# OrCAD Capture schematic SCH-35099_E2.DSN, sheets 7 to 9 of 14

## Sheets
7 03 System Power: size C
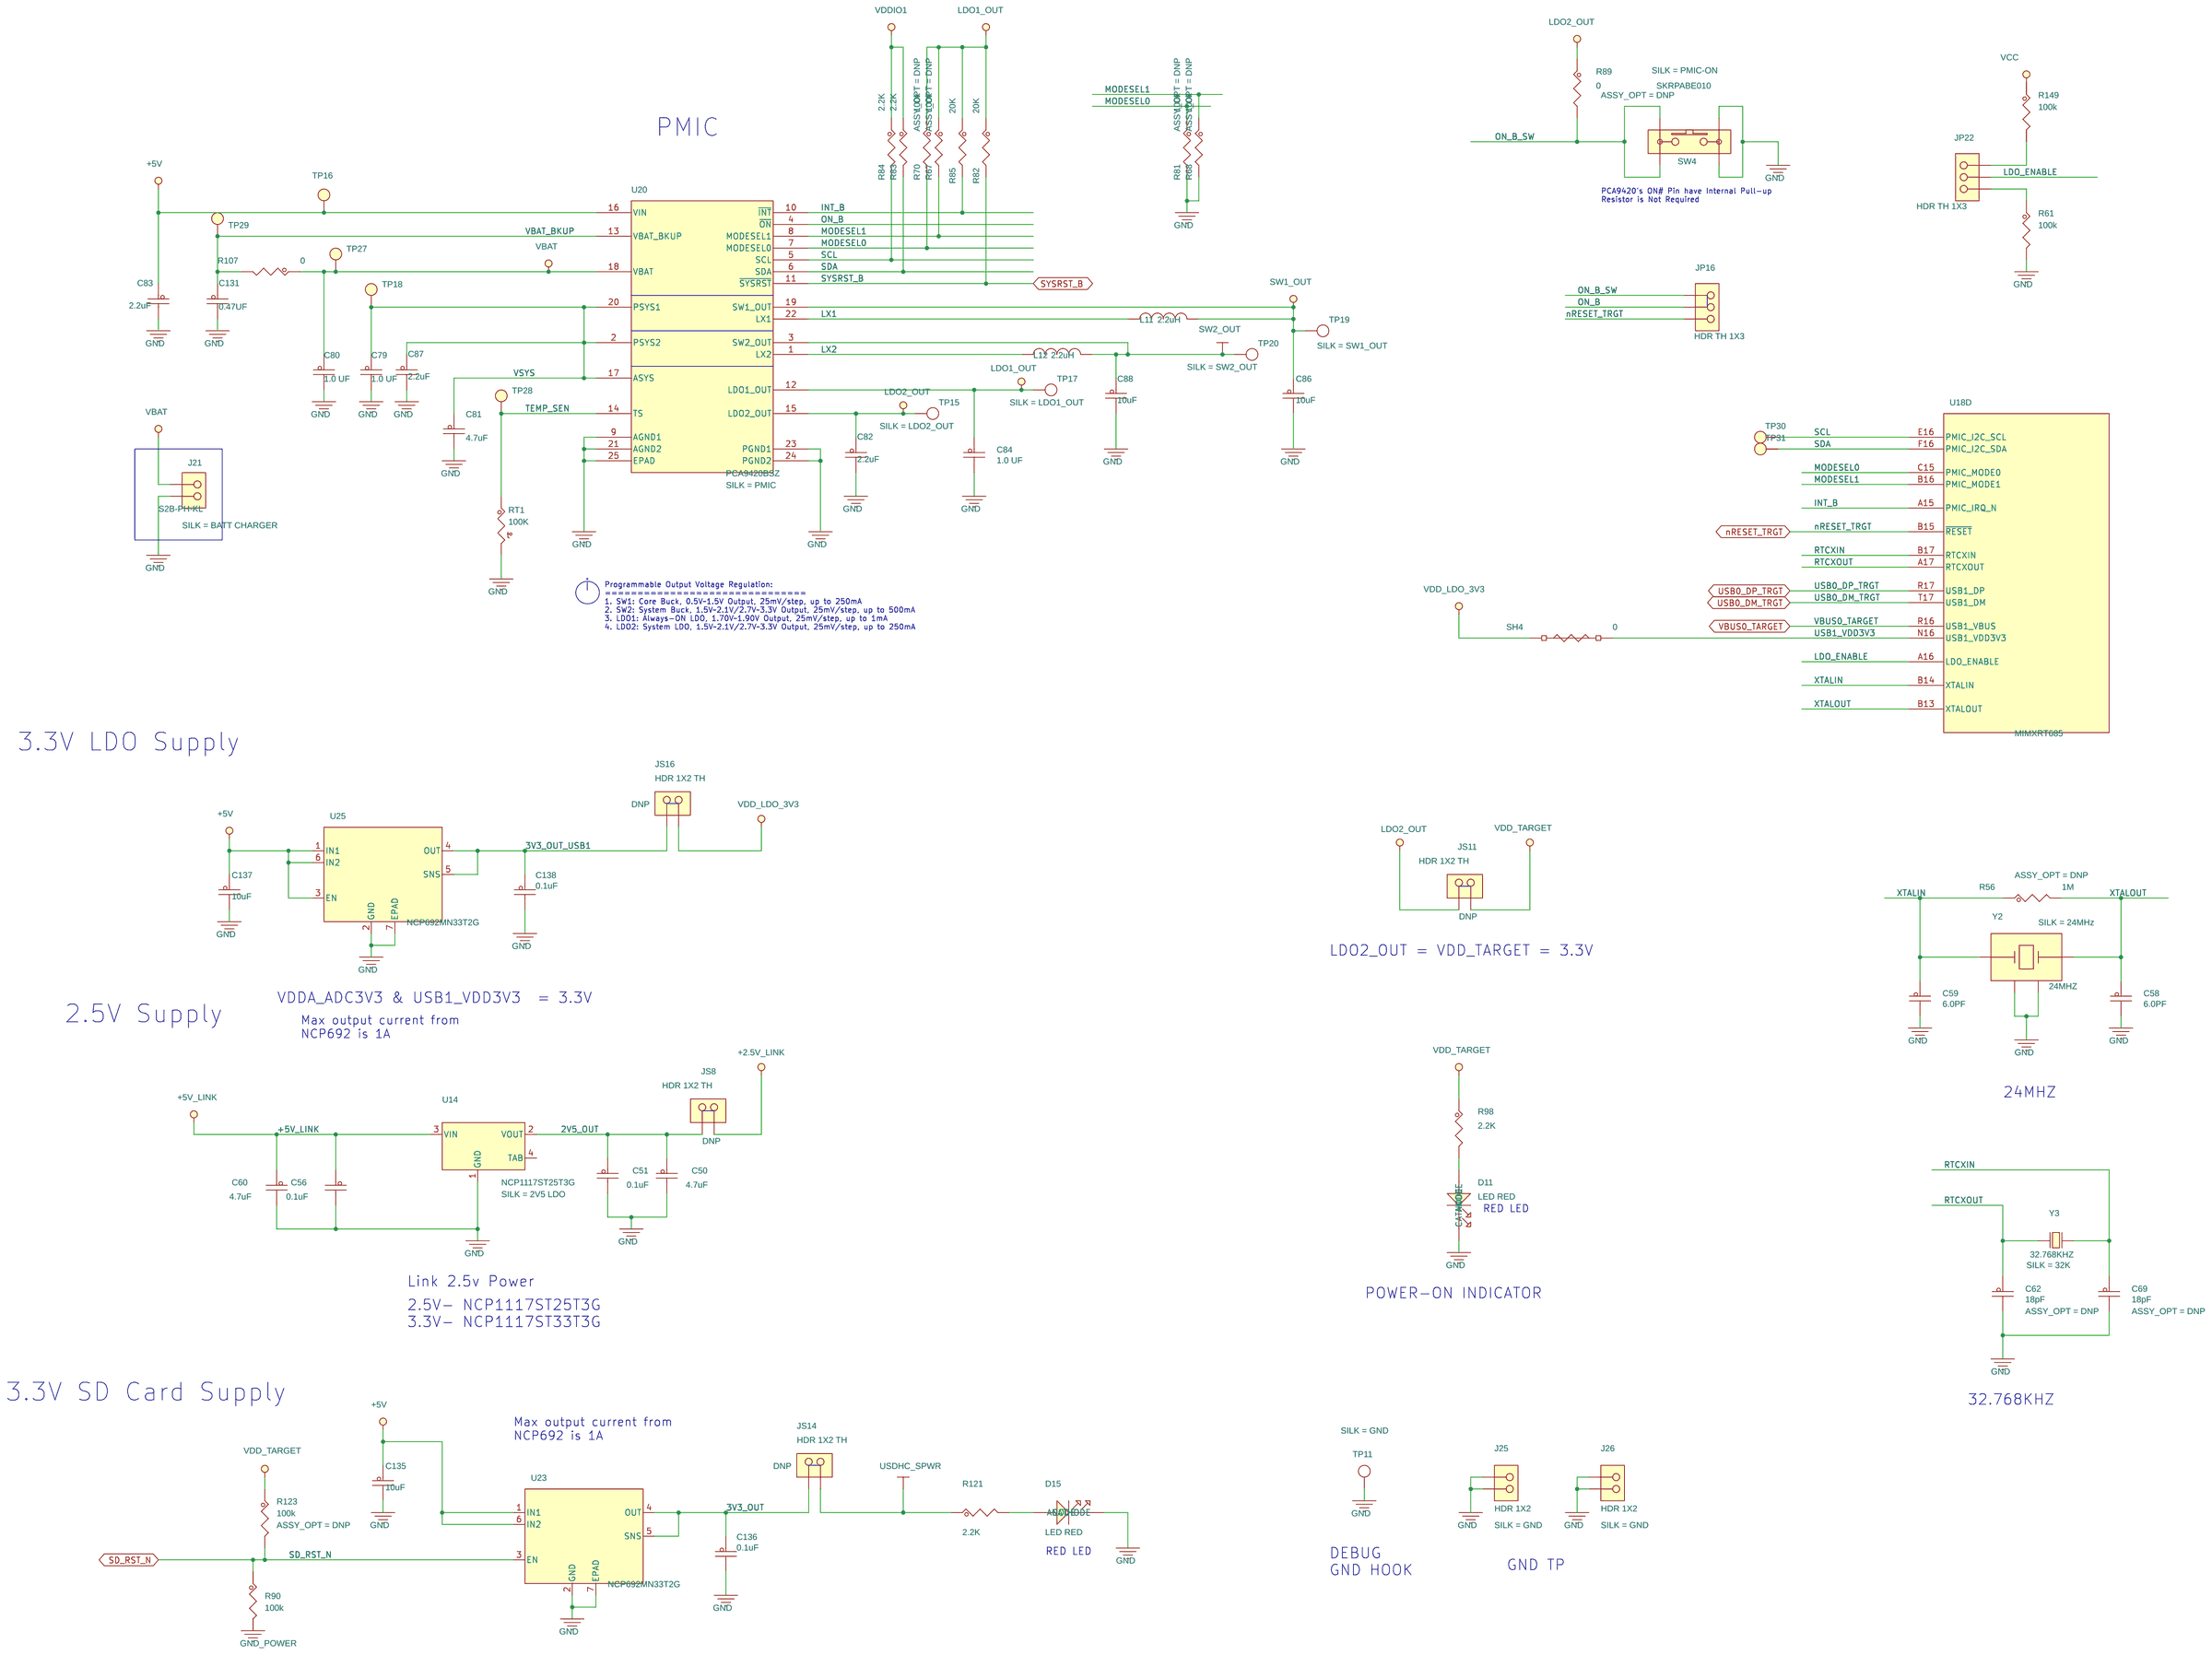
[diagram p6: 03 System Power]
8 04 RT6xx IO: size C
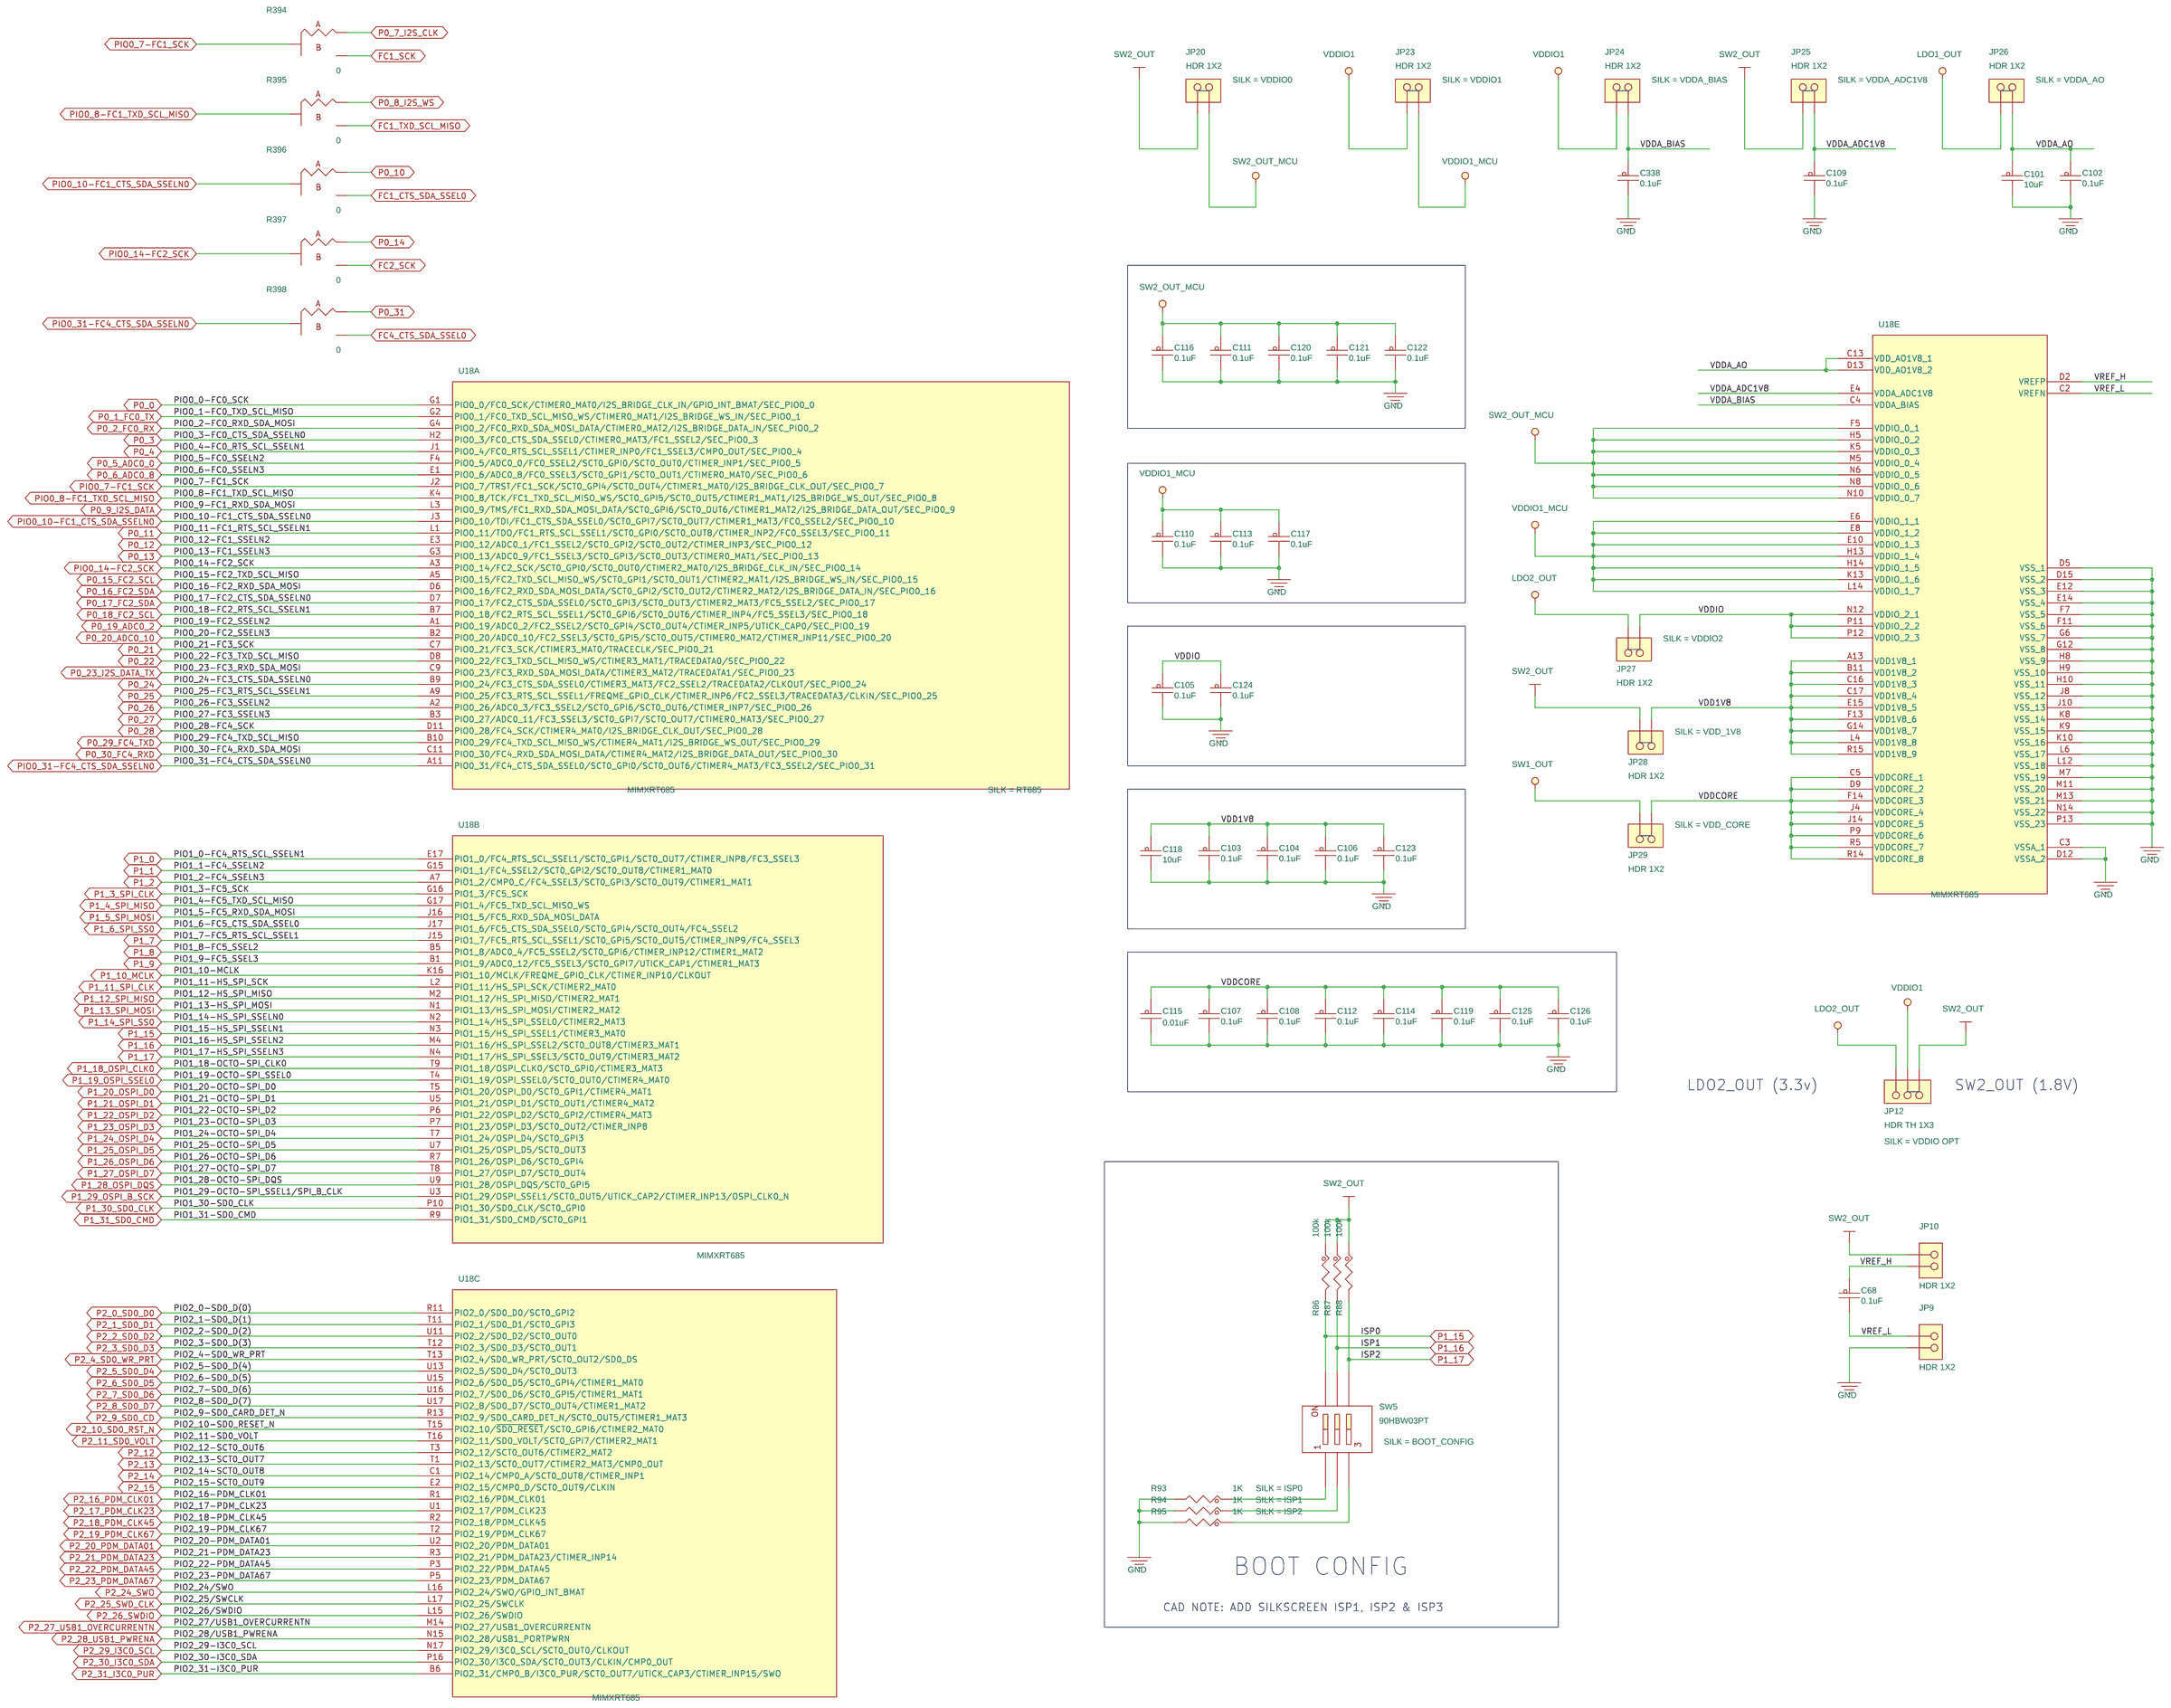
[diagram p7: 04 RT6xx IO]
9 05 Memory: size C
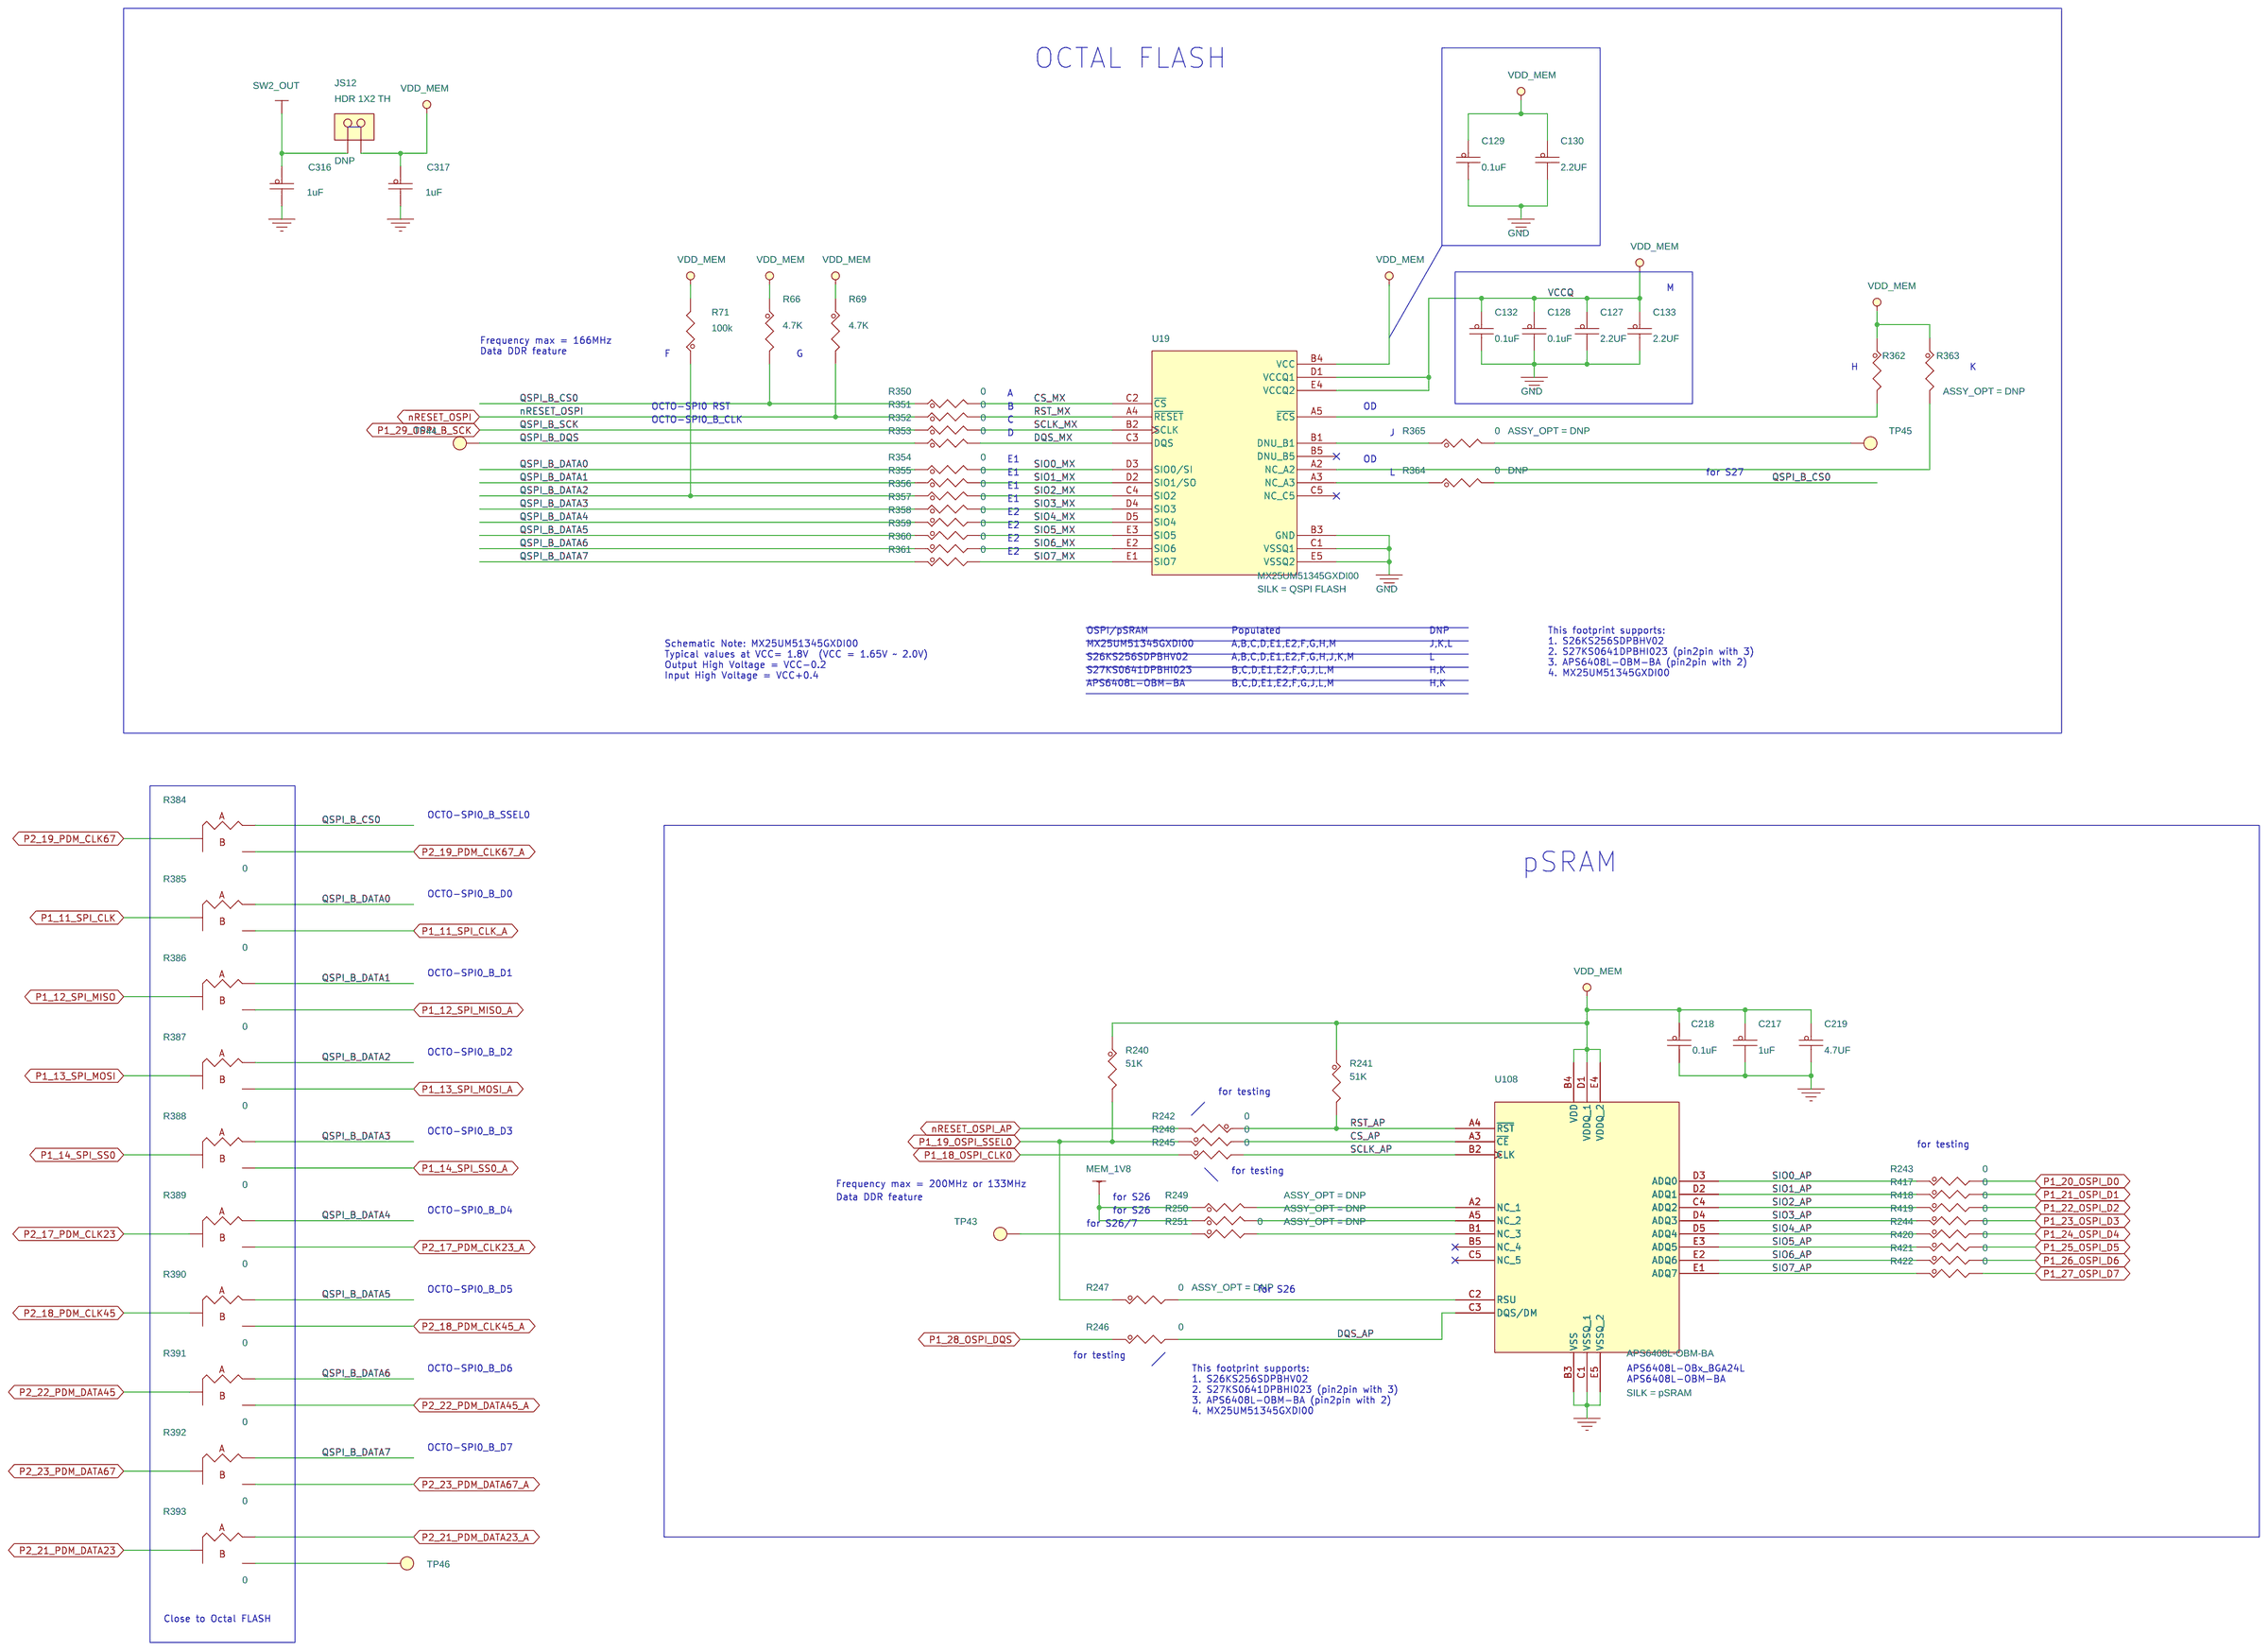
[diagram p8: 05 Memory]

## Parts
sheet 03 System Power
C50  4.7uF  [CC0603_OV]
C51  0.1uF  [CC0402_25]
C56  0.1uF  [CC0402_25]
C58  6.0PF  [CC0402_25]
C59  6.0PF  [CC0402_25]
C60  4.7uF  [CC0603_OV]
C62  18pF  [CC0402_25]
C69  18pF  [CC0402_25]
C79  1.0 UF  [CC0603_OV]
C80  1.0 UF  [CC0603_OV]
C81  4.7uF  [CC0603_OV]
C82  2.2uF  [cc0603_0402_nsp]
C83  2.2uF  [CC0603_OV]
C84  1.0 UF  [0603_CC]
C86  10uF  [cc0603_0805_nsp]
C87  2.2uF  [CC0603_OV]
C88  10uF  [cc0603_0805_nsp]
C131  0.47UF  [CC0603_OV]
C135  10uF  [cc0603_0805_nsp]
C136  0.1uF  [CC0402_25]
C137  10uF  [cc0603_0805_nsp]
C138  0.1uF  [CC0402_25]
D11  LED RED  [LED_0603]
D15  LED RED  [LED_0603]
J21  S2B-PH-KL  [HDR1X2_2P0_5P9X7P6]
J25  HDR 1X2  [HDR102]
J26  HDR 1X2  [HDR102]
JP16  HDR TH 1X3  [HDR103]
JP22  HDR TH 1X3  [HDR103]
JS8  HDR 1X2 TH  [SH_HDR102_BOTTOM]
JS11  HDR 1X2 TH  [SH_HDR102_BOTTOM]
JS14  HDR 1X2 TH  [SH_HDR102_BOTTOM]
JS16  HDR 1X2 TH  [SH_HDR102_BOTTOM]
L11  2.2uH  [ind_2016_2520_nsp]
L12  2.2uH  [ind_2016_2520_nsp]
R56  1M  [RC0402_25]
R61  100k  [RC0402_25]
R67  100k  [RC0402_25]
R68  100k  [RC0402_25]
R70  100k  [RC0402_25]
R81  100k  [RC0402_25]
R82  20K  [RC0603_OV]
R83  2.2K  [RC0402_25]
R84  2.2K  [RC0402_25]
R85  20K  [RC0603_OV]
R89  0  [RC0402_25]
R90  100k  [RC0402_25]
R98  2.2K  [RC0402_25]
R107  0  [RC0603_OV]
R121  2.2K  [RC0402_25]
R123  100k  [RC0402_25]
R149  100k  [RC0402_25]
RT1  100K  [RC0402_25]
SH4  0  [SH0603]
SW4  SKRPABE010  [sw4_skrp]
TP11  TEST POINT WHITE  [TEST_LOOP]
TP15  TEST POINT WHITE  [TEST_LOOP]
TP16  TPAD_050  [TPAD_050]
TP17  TEST POINT WHITE  [TEST_LOOP]
TP18  TPAD_050  [TPAD_050]
TP19  TEST POINT WHITE  [TEST_LOOP]
TP20  TEST POINT WHITE  [TEST_LOOP]
TP27  TPAD_050  [TPAD_050]
TP28  TPAD_050  [TPAD_050]
TP29  TPAD_050  [TPAD_050]
TP30  TPAD_050  [TPAD_050]
TP31  TPAD_050  [TPAD_050]
U14  NCP1117ST25T3G  [sot223]
U20  PCA9420BSZ  [hvqfn24_0p4_3p1x3p1_ep]
U23  NCP692MN33T2G  [dfn6_0p95_3x3]
U25  NCP692MN33T2G  [dfn6_0p95_3x3]
Y2  24MHZ  [xtlosc4_3p2x2p5mm_sm]
Y3  32.768KHZ  [XTAL2-3p2x1p5-SM]
sheet 04 RT6xx IO
C68  0.1uF  [CC0201]
C101  10uF  [CC0603_OV]
C102  0.1uF  [CC0201]
C103  0.1uF  [CC0201]
C104  0.1uF  [CC0201]
C105  0.1uF  [CC0201]
C106  0.1uF  [CC0201]
C107  0.1uF  [CC0201]
C108  0.1uF  [CC0201]
C109  0.1uF  [CC0201]
C110  0.1uF  [CC0201]
C111  0.1uF  [CC0201]
C112  0.1uF  [CC0201]
C113  0.1uF  [CC0201]
C114  0.1uF  [CC0201]
C115  0.01uF  [CC0201]
C116  0.1uF  [CC0201]
C117  0.1uF  [CC0201]
C118  10uF  [CC0603_OV]
C119  0.1uF  [CC0201]
C120  0.1uF  [CC0201]
C121  0.1uF  [CC0201]
C122  0.1uF  [CC0201]
C123  0.1uF  [CC0201]
C124  0.1uF  [CC0201]
C125  0.1uF  [CC0201]
C126  0.1uF  [CC0201]
C338  0.1uF  [CC0201]
JP9  HDR 1X2  [HDR102]
JP10  HDR 1X2  [HDR102]
JP12  HDR TH 1X3  [HDR103]
JP20  HDR 1X2  [HDR102]
JP23  HDR 1X2  [HDR102]
JP24  HDR 1X2  [HDR102]
JP25  HDR 1X2  [HDR102]
JP26  HDR 1X2  [HDR102]
JP27  HDR 1X2  [HDR102]
JP28  HDR 1X2  [HDR102]
JP29  HDR 1X2  [HDR102]
R86  100k  [RC0402_25]
R87  100k  [RC0402_25]
R88  100k  [RC0402_25]
R93  1K  [RC0402_25]
R94  1K  [RC0402_25]
R95  1K  [RC0402_25]
R394  0  [R603-X2]
R395  0  [R603-X2]
R396  0  [R603-X2]
R397  0  [R603-X2]
R398  0  [R603-X2]
SW5  90HBW03PT  [sw_dip6_2p54_7p37x9p65mm_sm]
U18  MIMXRT685  [bga176_0p5_9x9]  (sections A,B,C,D,E)
sheet 05 Memory
C127  2.2UF  [CC0402_25]
C128  0.1uF  [CC0402_25]
C129  0.1uF  [CC0402_25]
C130  2.2UF  [CC0402_25]
C132  0.1uF  [CC0402_25]
C133  2.2UF  [CC0402_25]
C217  1uF  [cc0402_tol0p15_ov]
C218  0.1uF  [CC0402_25]
C219  4.7UF  [cc0402_tol0p15_ov]
C316  1uF  [cc0402_tol0p15_ov]
C317  1uF  [cc0402_tol0p15_ov]
JS12  HDR 1X2 TH  [SH_HDR102_BOTTOM]
R66  4.7K  [RC0402_25]
R69  4.7K  [RC0402_25]
R71  100k  [RC0402_25]
R240  51K  [RC0402_25]
R241  51K  [RC0402_25]
R242  0  [RC0402_25]
R243  0  [RC0402_25]
R244  0  [RC0402_25]
R245  0  [RC0402_25]
R246  0  [RC0402_25]
R247  0  [RC0402_25]
R248  0  [RC0402_25]
R249  10K  [0402_CC]
R250  10K  [0402_CC]
R251  0  [RC0402_25]
R350  0  [RC0402_25]
R351  0  [RC0402_25]
R352  0  [RC0402_25]
R353  0  [RC0402_25]
R354  0  [RC0402_25]
R355  0  [RC0402_25]
R356  0  [RC0402_25]
R357  0  [RC0402_25]
R358  0  [RC0402_25]
R359  0  [RC0402_25]
R360  0  [RC0402_25]
R361  0  [RC0402_25]
R362  10K  [0402_CC]
R363  10K  [0402_CC]
R364  0  [RC0402_25]
R365  0  [RC0402_25]
R384  0  [R603-X2]
R385  0  [R603-X2]
R386  0  [R603-X2]
R387  0  [R603-X2]
R388  0  [R603-X2]
R389  0  [R603-X2]
R390  0  [R603-X2]
R391  0  [R603-X2]
R392  0  [R603-X2]
R393  0  [R603-X2]
R417  0  [RC0402_25]
R418  0  [RC0402_25]
R419  0  [RC0402_25]
R420  0  [RC0402_25]
R421  0  [RC0402_25]
R422  0  [RC0402_25]
TP43  TPAD_050  [TPAD_050]
TP44  TPAD_050  [TPAD_050]
TP45  TPAD_050  [TPAD_050]
TP46  TPAD_050  [TPAD_050]
U19  MX25UM51345GXDI00  [pbga24_1_6x8mm]
U108  APS6408L-OBM-BA  [pbga24_1_6x8mm]

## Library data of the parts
C50 C60 C81 = CAP_NP: CAP CER 4.7UF 10V 10% X5R 0603; AGILE_PN: 150-77975; CAD_APPROVED: Yes; FPLIST: CC0603_OV,CC0603,0603_CC; HEIGHT: 0.9MM; MFG_NAME01: TAIYO YUDEN; MFG_PN01: LMK107BJ475KA-T; Package Size: 0603; Package Type: tape & reel; ROHS: Yes; Tolerance: 10%; VOLTAGE: 10V
C51 C56 C128 C129 C132 C136 C138 C218 = CAP_NP: CAP CER 0.1UF 25V 20% X5R 0402; AGILE_PN: 150-80403; CAD_APPROVED: Yes; FPLIST: CC0402_25,CC0402_HD,0402_CC; HEIGHT: 0.55MM; MFG_NAME01: WURTH ELEKTRONIK EISOS GMBH & CO. KG (ELECTRONIC & ELECTROMEHANICAL COMP); MFG_PN01: 885012105018; ROHS: Yes; Temp Range: -55°C to +85°C; Temp_Range: -55°C to +125°C; VOLTAGE: 25V
C58 C59 = CAP_NP: CAP CER 6PF 50V 0.1PF C0G 0402; AGILE_PN: 150-77434; CAD_APPROVED: Yes; FPLIST: CC0402_25,CC0402_HD,0402_CC; HEIGHT: 0.55 MM; MFG_NAME01: YAGEO; MFG_PN01: CC0402BRNPO9BN6R0; ROHS: Yes; Tolerance: 0.1PF; VOLTAGE: 50V
C62 C69 = CAP_NP: CAP CER 18pF 25V 5% C0G 0402; AGILE_PN: 150-78760; ASSY_OPT: DNP; CAD_APPROVED: Yes; FPLIST: CC0402_25,CC0402_HD,0402_CC; HEIGHT: 0.56MM; MFG_NAME01: AVX; MFG_PN01: 04023A180JAT2A; ROHS: Yes; Tolerance: 5%; VOLTAGE: 25V
C79 C80 C84 = CAP_NP: CAP CER 1.0UF 16V 10% X7R 0603; AGILE_PN: 150-30028; CAD_APPROVED: Yes; FPLIST: CC0603_OV,CC0603,0603_CC; HEIGHT: 1.0MM; MFG_NAME01: AVX; MFG_PN01: 0603YC105KAT2A; Package Size: 603; Package Type: tape & reel; ROHS: Yes; Temp Range: -55°C to +125°C; Temp_Range: -55°C to +125°C; Tolerance: 10%; VOLTAGE: 16V
C82 C83 C87 = CAP_NP: CAP CER 2.2uF 16V 10% X7R 0603; AGILE_PN: 150-80122; CAD_APPROVED: Yes; FPLIST: CC0603_OV,CC0603,0603_CC,cc0603_0402_nsp; HEIGHT: 1MM; MFG_NAME01: MURATA; MFG_PN01: GRM188Z71C225KE43; ROHS: Yes; Temp Range: -55°C ~ 125°C; Temp_Range: -55°C ~ 125°C; Tolerance: 10%; VOLTAGE: 16V
C86 C88 C135 C137 = CAP_NP: CAP CER 10.0uF 16V 10% X7R 0805; AGILE_PN: 150-80121; CAD_APPROVED: Yes; FPLIST: CC0805_OV,CC0805,0805_CC,cc0603_0805_nsp; HEIGHT: 1.45MM; MFG_NAME01: MURATA; MFG_PN01: GRM21BZ71C106KE15; Package Size: 0805; Package Type: SMT; ROHS: Yes; Temp Range: -55C to +125C; Temp_Range: -55C to +125C; VOLTAGE: 16V
C131 = CAP_NP: CAP CER 0.47UF 16V 10% X5R 0603; AGILE_PN: 150-75194; CAD_APPROVED: Yes; FPLIST: CC0603_OV,CC0603,0603_CC; HEIGHT: 0.90MM; MFG_NAME01: KEMET; MFG_PN01: C0603C474K4PAC; Package Size: 0603; Package Type: tape & reel; ROHS: Yes; Tolerance: 10%; VOLTAGE: 16V
D11 D15 = LED: LED BRIGHT RED CLEAR SGL 2V 20MA SMT 0603; AGILE_PN: 370-76779; CAD_APPROVED: Yes; HEIGHT: 0.80MM; MFG_NAME01: WURTH ELEKTRONIK EISOS GMBH & CO. KG (ELECTRONIC & ELECTROMEHANICAL COMP); MFG_PN01: 150060RS75000; REQUESTED_COMPLETION_DATE: Not an expedite request; ROHS: Yes; VOLTAGE: 2V
J21 = CONN_HDR_2X1: HDR 1X2 TH RA 98MIL SP 189H SN --; AGILE_PN: 210-81489; CAD_APPROVED: Yes; HEIGHT: 4.8MM; MFG_NAME01: JST MFG. CO; MFG_PN01: S2B-PH-KL(LF)(SN); ROHS: Yes; SILK: BATT CHARGER; Temp Range: -25C to +85C; Temp_Range: -25C to +85C
J25 J26 = CONN_HDR_2X1: HDR 1X2 TH 100MIL SP 338H SN 100L; AGILE_PN: 210-80102; CAD_APPROVED: Yes; HEIGHT: 8.58MM; MFG_NAME01: SAMTEC; MFG_PN01: TSW-102-07-T-S; Package Size: 5.08 x 2.54 mm; ROHS: Yes; SILK: GND
JP16 JP22 = CONN_HDR_3X1: HDR 1X3 TH 100MIL SP 339H AU 100L; AGILE_PN: 210-75726; CAD_APPROVED: Yes; HEIGHT: 8.65MM; MFG_NAME01: SAMTEC; MFG_PN01: TSW-103-07-G-S; Package Size: 7.62 x 2.54 mm; ROHS: Yes; Temp Range: -55°C to +125°C; Temp_Range: -55°C to +125°C; VOLTAGE: 450 - 550 VAC
JS8 JS11 JS12 JS14 JS16 = CONN_HDR_2X1: HDR 1X2 TH 100MIL SP 339H AU 98L; AGILE_PN: 210-75439; ASSY_OPT: DNP; CAD_APPROVED: YES; FPLIST: HDR102,SH_HDR102_BOTTOM; HEIGHT: 8.71 MM; MFG_NAME01: SAMTEC; MFG_PN01: TSW-102-07-G-S; ROHS: Yes; Temp Range: -55°C to +125°C; Temp_Range: -55°C to +125°C
L11 L12 = INDUCTOR: IND PWR 2.2uH@1MHz 2.5A 20% 2016; AGILE_PN: 180-78704; CAD_APPROVED: Yes; FPLIST: ind_2016a,ind_2016_2520_nsp; HEIGHT: 1MM; MFG_NAME01: SAMSUNG ELECTRO MECHANICS; MFG_PN01: CIGT201610EH2R2MNE; PART_TYPE: INDUCTOR\POWER; ROHS: Yes; TOL: 20%; Temp Range: -40C to 125C; Temp_Range: -40C to 125C; Tolerance: 20%
R56 = RES: RES MF 1M 1/16W 1% 0402; AGILE_PN: 470-80575; ASSY_OPT: DNP; CAD_APPROVED: Yes; FPLIST: RC0402_25,RC0402_HD,0402_CC; HEIGHT: 0.4MM; MFG_NAME01: BOURNS; MFG_PN01: CR0402-FX-1004GLF; ROHS: Yes; Tolerance: 1%
R61 R71 R86-R88 R90 R149 = RES: RES MF 100K 1/16W 5% 100ppm/C 0402; AGILE_PN: 470-82058; CAD_APPROVED: Yes; FPLIST: RC0402_25,RC0402_HD,0402_CC; HEIGHT: 0.40 MM; MFG_NAME01: YAGEO AMERICA; MFG_PN01: RC0402JR-07100KL; ROHS: Yes; Temp Range: -55C to +155C; Tolerance: 5%; VOLTAGE: 50V
R67 R68 R70 R81 R123 = RES: RES MF 100K 1/16W 5% 100ppm/C 0402; AGILE_PN: 470-82058; ASSY_OPT: DNP; CAD_APPROVED: Yes; FPLIST: RC0402_25,RC0402_HD,0402_CC; HEIGHT: 0.40 MM; MFG_NAME01: YAGEO AMERICA; MFG_PN01: RC0402JR-07100KL; ROHS: Yes; Temp Range: -55C to +155C; Tolerance: 5%; VOLTAGE: 50V
R82 R85 = RES: RES MF 20K 1/10W 5% 0603; AGILE_PN: 470-75450; CAD_APPROVED: Yes; FPLIST: RC0603_OV,RC0603,0603_CC; HEIGHT: 0.55MM; MFG_NAME01: BOURNS; MFG_PN01: CR0603-JW-203ELF; ROHS: Yes; Tolerance: 5%; VOLTAGE: 50V
R83 R84 R98 R121 = RES: RES MF 2.2K 1/16W 5% 0402; AGILE_PN: 470-76602; CAD_APPROVED: Yes; FPLIST: RC0402_25,RC0402_HD,0402_CC; HEIGHT: 0.4 MM; MFG_NAME01: YAGEO AMERICA; MFG_PN01: RC0402JR-072K2L; ROHS: Yes; Temp_Range: -55C to +155C; Tolerance: 5%
R89 = RES: RES MF ZERO OHM 1/16W 5% 0402; AGILE_PN: 470-75394; ASSY_OPT: DNP; CAD_APPROVED: Yes; EN: 101-1-00001; FPLIST: RC0402_25,RC0402_HD,RC0402_X2,0402_CC; HEIGHT: 0.45 MM; KEY Number: 101-1-00001@2; MFG_NAME01: YAGEO AMERICA; MFG_PN01: RC0402JR-070RL; Mfg: VISHAY; Mfg Part No: CRCW04020000Z0**; ROHS: Yes; Temperature: -55°C to +155°C; Tolerance: 5%; VOLTAGE: 1/16W
R107 = RES: RES MF ZERO OHM 1/10W -- 0603; AGILE_PN: 470-80866; CAD_APPROVED: Yes; FPLIST: RC0603_OV,RC0603,R603-X2,0603_CC,IND_0603HP_NSP,CC0603_OV_NSP; HEIGHT: 0.6MM; MFG_NAME01: YAGEO AMERICA; MFG_PN01: RC0603FR-070RL; ROHS: Yes; Temp Range: –55 °C to +155 °C; Temp_Range: –55 °C to +155 °C
RT1 = THERMISTOR: RES THERMISTOR NTC 100K@25 DEGC 100mW 1% 0402; AGILE_PN: 470-81814; CAD_APPROVED: Yes; FPLIST: RC0402_25,RC0402_HD,0402_CC; HEIGHT: 0.55MM; MFG_NAME01: MURATA; MFG_PN01: NCP15WF104F03RC; ROHS: Yes; Temp Range: -40C to +125C; Temp_Range: -40C to +125C; Tolerance: 1%
SH4 = RES_SHORT-2: ZERO OHM CUT TRACE 0603 PADS; NO PART TO ORDER; AGILE_PN: 470-80018; CAD_APPROVED: Yes; FPLIST: SH0603,SH0603_CC,SH0603-X2_PIN1TO2; HEIGHT: 0.1MM; MFG_NAME01: LAYOUT ELEMENT ONLY; MFG_PN01: LAYOUT ELEMENT ONLY; ROHS: Yes
SW4 = SW_TC_SPST_4P: SW SPST PB SMT 16V 20MA; AGILE_PN: 510-75638; CAD_APPROVED: Yes; HEIGHT: 2.5MM; MFG_NAME01: ALPS ELECTRIC (USA) INC.; ROHS: Yes; SILK: PMIC-ON; VOLTAGE: 16V
TP11 = TESTLOOP: TEST POINT WHITE 40 MIL DRILL 180 MIL TH 109L; AGILE_PN: 210-75685; CAD_APPROVED: Yes; HEIGHT: 4.8 MM; MFG_NAME01: KEYSTONE ELECTRONICS; MFG_PN01: 5002; ROHS: Yes; SILK: GND; Temp Range: -50°C to +146°C; Temp_Range: -50°C to +146°C
TP15 = TESTLOOP: TEST POINT WHITE 40 MIL DRILL 180 MIL TH 109L; AGILE_PN: 210-75685; CAD_APPROVED: Yes; HEIGHT: 4.8 MM; MFG_NAME01: KEYSTONE ELECTRONICS; MFG_PN01: 5002; ROHS: Yes; SILK: LDO2_OUT; Temp Range: -50°C to +146°C; Temp_Range: -50°C to +146°C
TP16 TP18 TP27-TP31 TP43-TP46 = TEST_POINT_L: TEST POINT PAD 50MIL DIA SMT, NO PART TO ORDER; AGILE_PN: 211-76644; CAD_APPROVED: Yes; EN: 666-1-00186; HEIGHT: 0.1MM; KEY Number: 666-1-00186@1; MFG_NAME01: NOTACOMPONENT; MFG_PN01: NOTACOMPONENT; Mfg: NA; Mfg Part No: 666-1-00186; ROHS: Yes
TP17 = TESTLOOP: TEST POINT WHITE 40 MIL DRILL 180 MIL TH 109L; AGILE_PN: 210-75685; CAD_APPROVED: Yes; HEIGHT: 4.8 MM; MFG_NAME01: KEYSTONE ELECTRONICS; MFG_PN01: 5002; ROHS: Yes; SILK: LDO1_OUT; Temp Range: -50°C to +146°C; Temp_Range: -50°C to +146°C
TP19 = TESTLOOP: TEST POINT WHITE 40 MIL DRILL 180 MIL TH 109L; AGILE_PN: 210-75685; CAD_APPROVED: Yes; HEIGHT: 4.8 MM; MFG_NAME01: KEYSTONE ELECTRONICS; MFG_PN01: 5002; ROHS: Yes; SILK: SW1_OUT; Temp Range: -50°C to +146°C; Temp_Range: -50°C to +146°C
TP20 = TESTLOOP: TEST POINT WHITE 40 MIL DRILL 180 MIL TH 109L; AGILE_PN: 210-75685; CAD_APPROVED: Yes; HEIGHT: 4.8 MM; MFG_NAME01: KEYSTONE ELECTRONICS; MFG_PN01: 5002; ROHS: Yes; SILK: SW2_OUT; Temp Range: -50°C to +146°C; Temp_Range: -50°C to +146°C
U14 = LD1117AS18: IC VREG LDO 2.5V 1A 20V SOT-223; AGILE_PN: 315-80698; CAD_APPROVED: Yes; HEIGHT: 1.8MM; MFG_NAME01: ON Semiconductor; ROHS: Yes; SILK: 2V5 LDO
U20 = PCA9420KBS_HVQFN24: IC PWR 4CH PMIC PROGRAMMABLE 3.3-5.5V QFN24; AGILE_PN: TMP-CIP-312; HEIGHT: 1MM; MFG_NAME01: NXP SEMICONDUCTORS; PRE_APN: 312-82357; Package Size: 3x3x1mm; SILK: PMIC
U23 U25 = NCP692_6P: IC VREG LDO 3.3V 1A 6V DFN6; AGILE_PN: 315-79987; CAD_APPROVED: Yes; HEIGHT: 1MM; MFG_NAME01: ON SEMICONDUCTOR; ROHS: Yes; VOLTAGE: 6V
Y2 = XTAL_13: XTAL 24MHZ 9pF -- SMT 3.2X2.5MM; AGILE_PN: 230-77392; CAD_APPROVED: Yes; HEIGHT: 0.60MM; MFG_NAME01: EPSON TOYOCOM CORPORATION; MFG_PN01: TSX-3225 24.0000MF15X-AC3; ROHS: Yes; SILK: 24MHz
Y3 = CRYSTAL: XTAL 32.768KHZ 7PF 20PPM -- SMT; AGILE_PN: 230-78102; CAD_APPROVED: Yes; HEIGHT: 0.9MM; MFG_NAME01: EPSON ELECTRONICS; MFG_PN01: FC-135 32.7680KA-AG3; ROHS: Yes; SILK: 32K
C68 C102-C114 C116 C117 C119-C126 C338 = CAP_NP: CAP CER 0.1uF 16V 10% X7R 0201; AGILE_PN: 150-80124; CAD_APPROVED: Yes; FPLIST: CC0201,CC0201_HD,0201_CC; HEIGHT: 0.33MM; MFG_NAME01: MURATA; MFG_PN01: GRM033Z71C104KE14; Package Size: 0201; ROHS: Yes; Temp Range: -55°C ~ 125°C; Temp_Range: -55°C ~ 125°C; Tolerance: 10%; VOLTAGE: 16V
C101 C118 = CAP_NP: CAP CER 10uF 16V 20% X5R 0603; AGILE_PN: 150-80336; CAD_APPROVED: Yes; FPLIST: CC0603_OV,CC0603; HEIGHT: 1MM; MFG_NAME01: MURATA; MFG_PN01: GRM188R61C106MA73D; Package Size: 0603; Package Type: SMD; ROHS: Yes; Tolerance: 20%; VOLTAGE: 16V
C115 = CAP_NP: CAP CER 0.01uF 16V 10% X7R 0201; AGILE_PN: 150-80313; CAD_APPROVED: Yes; FPLIST: CC0201,CC0201_HD,0201_CC; HEIGHT: 0.33MM; MFG_NAME01: MURATA; MFG_PN01: GRM033R71C103KE14D; Package Size: 0201; ROHS: Yes; Temp Range: -55 to 125°C; Temp_Range: -55 to 125°C; Tolerance: 10%; VOLTAGE: 16V
JP9 JP10 = CONN_HDR_2X1: HDR 1X2 TH 100MIL SP 338H SN 100L; AGILE_PN: 210-80102; CAD_APPROVED: Yes; HEIGHT: 8.58MM; MFG_NAME01: SAMTEC; MFG_PN01: TSW-102-07-T-S; Package Size: 5.08 x 2.54 mm; ROHS: Yes
JP12 = CONN_HDR_3X1: HDR 1X3 TH 100MIL SP 339H AU 100L; AGILE_PN: 210-75726; CAD_APPROVED: Yes; HEIGHT: 8.65MM; MFG_NAME01: SAMTEC; MFG_PN01: TSW-103-07-G-S; Package Size: 7.62 x 2.54 mm; ROHS: Yes; SILK: VDDIO OPT; Temp Range: -55°C to +125°C; Temp_Range: -55°C to +125°C; VOLTAGE: 450 - 550 VAC
JP20 = CONN_HDR_2X1: HDR 1X2 TH 100MIL SP 338H SN 100L; AGILE_PN: 210-80102; CAD_APPROVED: Yes; HEIGHT: 8.58MM; MFG_NAME01: SAMTEC; MFG_PN01: TSW-102-07-T-S; Package Size: 5.08 x 2.54 mm; ROHS: Yes; SILK: VDDIO0
JP23 = CONN_HDR_2X1: HDR 1X2 TH 100MIL SP 338H SN 100L; AGILE_PN: 210-80102; CAD_APPROVED: Yes; HEIGHT: 8.58MM; MFG_NAME01: SAMTEC; MFG_PN01: TSW-102-07-T-S; Package Size: 5.08 x 2.54 mm; ROHS: Yes; SILK: VDDIO1
JP24 = CONN_HDR_2X1: HDR 1X2 TH 100MIL SP 338H SN 100L; AGILE_PN: 210-80102; CAD_APPROVED: Yes; HEIGHT: 8.58MM; MFG_NAME01: SAMTEC; MFG_PN01: TSW-102-07-T-S; Package Size: 5.08 x 2.54 mm; ROHS: Yes; SILK: VDDA_BIAS
JP25 = CONN_HDR_2X1: HDR 1X2 TH 100MIL SP 338H SN 100L; AGILE_PN: 210-80102; CAD_APPROVED: Yes; HEIGHT: 8.58MM; MFG_NAME01: SAMTEC; MFG_PN01: TSW-102-07-T-S; Package Size: 5.08 x 2.54 mm; ROHS: Yes; SILK: VDDA_ADC1V8
JP26 = CONN_HDR_2X1: HDR 1X2 TH 100MIL SP 338H SN 100L; AGILE_PN: 210-80102; CAD_APPROVED: Yes; HEIGHT: 8.58MM; MFG_NAME01: SAMTEC; MFG_PN01: TSW-102-07-T-S; Package Size: 5.08 x 2.54 mm; ROHS: Yes; SILK: VDDA_AO
JP27 = CONN_HDR_2X1: HDR 1X2 TH 100MIL SP 338H SN 100L; AGILE_PN: 210-80102; CAD_APPROVED: Yes; HEIGHT: 8.58MM; MFG_NAME01: SAMTEC; MFG_PN01: TSW-102-07-T-S; Package Size: 5.08 x 2.54 mm; ROHS: Yes; SILK: VDDIO2
JP28 = CONN_HDR_2X1: HDR 1X2 TH 100MIL SP 338H SN 100L; AGILE_PN: 210-80102; CAD_APPROVED: Yes; HEIGHT: 8.58MM; MFG_NAME01: SAMTEC; MFG_PN01: TSW-102-07-T-S; Package Size: 5.08 x 2.54 mm; ROHS: Yes; SILK: VDD_1V8
JP29 = CONN_HDR_2X1: HDR 1X2 TH 100MIL SP 338H SN 100L; AGILE_PN: 210-80102; CAD_APPROVED: Yes; HEIGHT: 8.58MM; MFG_NAME01: SAMTEC; MFG_PN01: TSW-102-07-T-S; Package Size: 5.08 x 2.54 mm; ROHS: Yes; SILK: VDD_CORE
R93 = RES: RES MF 1.0K 1/16W 5% 0402; AGILE_PN: 470-75555; CAD_APPROVED: Yes; FPLIST: RC0402_25,RC0402_HD,RC0402_X2,0402_CC; HEIGHT: 0.41mm; MFG_NAME01: VISHAY INTERTECHNOLOGY; MFG_PN01: CRCW04021K00JNED; ROHS: Yes; SILK: ISP0; Tolerance: 5%
R94 = RES: RES MF 1.0K 1/16W 5% 0402; AGILE_PN: 470-75555; CAD_APPROVED: Yes; FPLIST: RC0402_25,RC0402_HD,RC0402_X2,0402_CC; HEIGHT: 0.41mm; MFG_NAME01: VISHAY INTERTECHNOLOGY; MFG_PN01: CRCW04021K00JNED; ROHS: Yes; SILK: ISP1; Tolerance: 5%
R95 = RES: RES MF 1.0K 1/16W 5% 0402; AGILE_PN: 470-75555; CAD_APPROVED: Yes; FPLIST: RC0402_25,RC0402_HD,RC0402_X2,0402_CC; HEIGHT: 0.41mm; MFG_NAME01: VISHAY INTERTECHNOLOGY; MFG_PN01: CRCW04021K00JNED; ROHS: Yes; SILK: ISP2; Tolerance: 5%
R384-R398 = RES_3PIN: RES MF ZERO OHM 1/10W -- 0603; AGILE_PN: 470-80866; CAD_APPROVED: Yes; FPLIST: RC0603_OV,RC0603,R603-X2,0603_CC,IND_0603HP_NSP,CC0603_OV_NSP; HEIGHT: 0.6MM; MFG_NAME01: YAGEO AMERICA; MFG_PN01: RC0603FR-070RL; ROHS: Yes; Temp Range: –55 °C to +155 °C; Temp_Range: –55 °C to +155 °C
SW5 = SW_DIP-3: SW SPST 3POS DIP 30V 0.15A SMT; AGILE_PN: 510-75116; CAD_APPROVED: Yes; HEIGHT: 4.83MM; MFG_NAME01: GRAYHILL; ROHS: Yes; SILK: BOOT_CONFIG; VOLTAGE: 30V
U18 = MIMXRT685EVKA_176P: IC MCU 32BIT 4.5MB SRAM 180MHZ 1.71-3.6V BGA176; AGILE_PN: TMP-WF-34557; CAD_APPROVED: Yes; HEIGHT: 1MM; MFG_NAME01: NXP SEMICONDUCTORS; MFG_PN01: MIMXRT685EVKA; PRE_APN: 344-02342; ROHS: Yes; SILK: RT685; Temp Range: 0 to 70 C; Temp_Range: 0 to 70 C; VOLTAGE: 1.71-3.6V
C127 C133 = CAP_NP: CAP CER 2.2UF 10V 20% X5R 0402; AGILE_PN: 150-79665; CAD_APPROVED: Yes; FPLIST: CC0402_25,CC0402_HD,0402_CC; HEIGHT: 0.55 MM; MFG_NAME01: MURATA; MFG_PN01: GRM155R61A225ME01D; ROHS: Yes; Tolerance: 20%; VOLTAGE: 10V
C130 = CAP_NP: CAP CER 2.2UF 10V 10% X5R 0402; AGILE_PN: 150-79475; CAD_APPROVED: Yes; FPLIST: CC0402_25,CC0402_HD,0402_CC; HEIGHT: 0.56MM; MFG_NAME01: AVX; MFG_PN01: 0402ZD225KAT2A; Package Size: 0402; ROHS: Yes; Tolerance: 10%; VOLTAGE: 10V
C217 C316 C317 = CAP_NP: CAP CER 1uF 10V 20% X6S 0402; AGILE_PN: 150-80349; CAD_APPROVED: Yes; FPLIST: CC0402_25,CC0402_HD,0402_CC; HEIGHT: 0.33 MM; MFG_NAME01: TDK; MFG_PN01: CGB2A1X6S1A105M033BC; Package Size: 0402; ROHS: Yes; Temp Range: -55 to +105°C; Tolerance: +/-20%; VOLTAGE: 10V
C219 = CAP_NP: CAP CER 4.7uF 10V 20% X5R 0402_WIDE; AGILE_PN: 150-79667; CAD_APPROVED: Yes; FPLIST: CC0402_25,CC0402_HD,0402_CC; HEIGHT: 0.7 MM; MFG_NAME01: MURATA; MFG_PN01: GRM155R61A475MEAA; Package Size: 0402; ROHS: Yes; Temp Range: -55 to 85; Temp_Range: -55 to 85; Tolerance: 20%; VOLTAGE: 10V
R66 R69 = RES: RES MF 4.7K 1/16W 5% 100ppm/C 0402; AGILE_PN: 470-82066; CAD_APPROVED: Yes; FPLIST: RC0402_25,RC0402_HD,0402_CC,RC0402_X2; HEIGHT: 0.41mm; MFG_NAME01: YAGEO AMERICA; MFG_PN01: RC0402JR-074K7L; ROHS: Yes; Temp Range: -55C to +155C; Tolerance: 5%; VOLTAGE: 50V
R240 R241 = RES: RES MF 51K 1/16W 5% 0402; AGILE_PN: 470-30449; CAD_APPROVED: Yes; FPLIST: RC0402_25,RC0402_HD,0402_CC; HEIGHT: 0.4MM; MFG_NAME01: VENKEL COMPANY; MFG_PN01: CR0402-16W-513JT; ROHS: Yes; Tolerance: 5%; VOLTAGE: 1/16W
R242-R246 R248 R350-R361 R417-R422 = RES: RES MF ZERO OHM 1/16W -- AEC-Q200 0402; AGILE_PN: 470-81849; CAD_APPROVED: Yes; FPLIST: RC0402_25,RC0402_HD,0402_CC; HEIGHT: 0.45 MM; MFG_NAME01: STACKPOLE ELECTRONICS; MFG_PN01: RMCF0402ZT0R00; ROHS: Yes
R247 R251 R364 R365 = RES: RES MF ZERO OHM 1/16W -- AEC-Q200 0402; AGILE_PN: 470-81849; ASSY_OPT: DNP; CAD_APPROVED: Yes; FPLIST: RC0402_25,RC0402_HD,0402_CC; HEIGHT: 0.45 MM; MFG_NAME01: STACKPOLE ELECTRONICS; MFG_PN01: RMCF0402ZT0R00; ROHS: Yes
R249 R250 R363 = RES: RES MF 10K 1/16W 5% 0402; AGILE_PN: 470-75557; ASSY_OPT: DNP; CAD_APPROVED: Yes; FPLIST: RC0402_25,RC0402_HD,0402_CC; HEIGHT: 0.4 MM; MFG_NAME01: VISHAY INTERTECHNOLOGY; MFG_PN01: CRCW040210K0JNED; ROHS: Yes; TOL: 5%; Tolerance: 5%
R362 = RES: RES MF 10K 1/16W 5% 0402; AGILE_PN: 470-75557; CAD_APPROVED: Yes; FPLIST: RC0402_25,RC0402_HD,0402_CC; HEIGHT: 0.4 MM; MFG_NAME01: VISHAY INTERTECHNOLOGY; MFG_PN01: CRCW040210K0JNED; ROHS: Yes; TOL: 5%; Tolerance: 5%
U19 = MX25UM51345GXD: IC MEM FLASH 512 Mbit (64 Mbyte) Octal SPI 1.8V 200MHz DTR BGA24; AGILE_PN: 342-00785; CAD_APPROVED: Yes; HEIGHT: 1.2MM; MFG_NAME01: MACRONIX INTERNATIONAL CO., LTD; ROHS: Yes; SILK: QSPI FLASH; Temp Range: -40°C ~ 85°C; Temp_Range: -40°C ~ 85°C; VOLTAGE: 1.8V
U108 = APS6408L-OBx_BGA24L: IC MEM DDR OCTAL SPI PSRAM 1.8V MINIBGA24L; AGILE_PN: TMP-WF-35383; CAD_APPROVED: Yes; HEIGHT: 1.2MM; MFG_NAME01: AP MEMORY; PRE_APN: 312-82205; ROHS: Yes; SILK: pSRAM; Temp Range: -25C to 85C; Temp_Range: -25C to 85C

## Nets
2V5_OUT: C50.1 C51.1 JS8.1 U14.2(VOUT)
3V3_OUT: C136.1 JS14.2 U23.4(OUT) U23.5(SNS)
3V3_OUT_USB1: C138.1 JS16.2 U25.4(OUT) U25.5(SNS)
+2.5V_LINK: JS8.2 ; also on sheet 11 12
+5V: C83.1 C135.1 C137.1 TP16.1(TP) U20.16(VIN) U23.1(IN1) U23.6(IN2) U25.1(IN1) U25.3(EN) U25.6(IN2) ; also on sheet 2 14
+5V_LINK: C56.1 C60.1 U14.3(VIN) ; also on sheet 2
GND: C50.2 C51.2 C56.2 C58.2 C59.2 C60.2 C62.2 C69.2 C79.2 C80.2 C81.2 C82.2 C83.2 C84.2 C86.2 C87.2 C88.2 C101.2 C102.2 C103.2 C104.2 C105.2 C106.2 C107.2 C108.2 C109.2 C110.2 C111.2 C112.2 C113.2 C114.2 C115.2 C116.2 C117.2 C118.2 C119.2 C120.2 C121.2 C122.2 C123.2 C124.2 C125.2 C126.2 C127.2 C128.2 C129.2 C130.2 C131.2 C132.2 C133.2 C135.2 C136.2 C137.2 C138.2 C217.2 C218.2 C219.2 C316.2 C317.2 C338.2 D11.C(CATHODE) D15.C(CATHODE) J21.2 J25.1 J25.2 J26.1 J26.2 JP9.2 R61.2 R68.2 R81.2 R90.2 R93.2 R94.2 R95.2 RT1.2 SW4.1 SW4.2 TP11.1(Pin1) U14.1(GND) U18.C3(VSSA_1) U18.D5(VSS_1) U18.D12(VSSA_2) U18.D15(VSS_2) U18.E12(VSS_3) U18.E14(VSS_4) U18.F7(VSS_5) U18.F11(VSS_6) U18.G6(VSS_7) U18.G12(VSS_8) U18.H8(VSS_9) U18.H9(VSS_10) U18.H10(VSS_11) U18.J8(VSS_12) U18.J10(VSS_13) U18.K8(VSS_14) U18.K9(VSS_15) U18.K10(VSS_16) U18.L6(VSS_17) U18.L12(VSS_18) U18.M7(VSS_19) U18.M11(VSS_20) U18.M13(VSS_21) U18.N14(VSS_22) U18.P13(VSS_23) U19.B3(GND) U19.C1(VSSQ1) U19.E5(VSSQ2) U20.9(AGND1) U20.21(AGND2) U20.23(PGND1) U20.24(PGND2) U20.25(EPAD) U23.2(GND) U23.7(EPAD) U25.2(GND) U25.7(EPAD) U108.B3(VSS) U108.C1(VSSQ_1) U108.E5(VSSQ_2) Y2.2 Y2.4 ; also on sheet 1 2 3 4 5 10 11 12 13 14
VBAT: C80.1 J21.1 R107.1 TP27.1(TP) U20.18(VBAT)
VBAT_BKUP: C131.1 R107.2 TP29.1(TP) U20.13(VBAT_BKUP)
VBUS0_TARGET: U18.R16(USB1_VBUS) ; also on sheet 2
VDD1V8: C103.1 C104.1 C106.1 C118.1 C123.1 JP28.1 U18.A13(VDD1V8_1) U18.B11(VDD1V8_2) U18.C16(VDD1V8_3) U18.C17(VDD1V8_4) U18.E15(VDD1V8_5) U18.F13(VDD1V8_6) U18.G14(VDD1V8_7) U18.L4(VDD1V8_8) U18.R15(VDD1V8_9)
VDD_LDO_3V3: JS16.1 SH4.1 ; also on sheet 2 10 14
VDD_MEM: C127.1 C128.1 C129.1 C130.1 C132.1 C133.1 C217.1 C218.1 C219.1 C317.1 JS12.1 R66.1 R69.1 R71.2 R240.1 R241.1 R362.1 R363.1 U19.B4(VCC) U19.D1(VCCQ1) U19.E4(VCCQ2) U108.B4(VDD) U108.D1(VDDQ_1) U108.E4(VDDQ_2)
VDD_TARGET: JS11.2 R98.1 R123.1 ; also on sheet 4 10
VDDA_ADC1V8: C109.1 JP25.2 U18.E4(VDDA_ADC1V8)
VDDA_AO: C101.1 C102.1 JP26.2 U18.C13(VDD_AO1V8_1) U18.D13(VDD_AO1V8_2)
VDDA_BIAS: C338.1 JP24.2 U18.C4(VDDA_BIAS)
VDDCORE: C107.1 C108.1 C112.1 C114.1 C115.1 C119.1 C125.1 C126.1 JP29.1 U18.C5(VDDCORE_1) U18.D9(VDDCORE_2) U18.F14(VDDCORE_3) U18.J4(VDDCORE_4) U18.J14(VDDCORE_5) U18.P9(VDDCORE_6) U18.R5(VDDCORE_7) U18.R14(VDDCORE_8)
VDDIO: C105.1 C124.1 JP27.1 U18.N12(VDDIO_2_1) U18.P11(VDDIO_2_2) U18.P12(VDDIO_2_3)
VDDIO1: JP12.2 JP23.1 JP24.1 R83.1 R84.1 ; also on sheet 2 4 5 10 12 13 14
VDDIO1_MCU: C110.1 C113.1 C117.1 JP23.2 U18.E6(VDDIO_1_1) U18.E8(VDDIO_1_2) U18.E10(VDDIO_1_3) U18.H13(VDDIO_1_4) U18.H14(VDDIO_1_5) U18.K13(VDDIO_1_6) U18.L14(VDDIO_1_7)
CS_AP: R248.2 U108.A3(~{CE})
CS_MX: R350.2 U19.C2(~{CS})
DQS_AP: R246.2 U108.C3(DQS/DM)
DQS_MX: R353.2 U19.C3(DQS)
FC1_CTS_SDA_SSEL0: R396.3 ; also on sheet 1 14
FC1_SCK: R394.3 ; also on sheet 14
FC1_TXD_SCL_MISO: R395.3 ; also on sheet 14
FC2_SCK: R397.3 ; also on sheet 14
FC4_CTS_SDA_SSEL0: R398.3 ; also on sheet 14
INT_B: R85.2 U18.A15(PMIC_IRQ_N) U20.10(~{INT})
LDO1_OUT: C84.1 JP26.1 R67.1 R70.1 R82.1 R85.1 R149.1 TP17.1(Pin1) U20.12(LDO1_OUT) ; also on sheet 4 14
LDO2_OUT: C82.1 JP12.3 JP27.2 JS11.1 R89.1 TP15.1(Pin1) U20.15(LDO2_OUT) ; also on sheet 3
LDO_ENABLE: JP22.2 U18.A16(LDO_ENABLE)
LX1: L11.1 U20.22(LX1)
LX2: L12.1 U20.1(LX2)
MEM_1V8: R249.1 R250.1
MODESEL0: R70.2 R81.1 U18.C15(PMIC_MODE0) U20.7(MODESEL0)
MODESEL1: R67.2 R68.1 U18.B16(PMIC_MODE1) U20.8(MODESEL1)
nRESET_OSPI: R69.2 R351.1 ; also on sheet 4
nRESET_OSPI_AP: R242.2 ; also on sheet 4
nRESET_TRGT: JP16.3 U18.B15(~{RESET}) ; also on sheet 4 5 10 12 14
ON_B: JP16.2 U20.4(~{ON})
ON_B_SW: JP16.1 R89.2 SW4.3 SW4.4
P0_0: U18.G1(PIO0_0/FC0_SCK/CTIMER0_MAT0/I2S_BRIDGE_CLK_IN/GPIO_INT_BMAT/SEC_PIO0_0) ; also on sheet 13
P0_1_FC0_TX: U18.G2(PIO0_1/FC0_TXD_SCL_MISO_WS/CTIMER0_MAT1/I2S_BRIDGE_WS_IN/SEC_PIO0_1) ; also on sheet 11 14
P0_2_FC0_RX: U18.G4(PIO0_2/FC0_RXD_SDA_MOSI_DATA/CTIMER0_MAT2/I2S_BRIDGE_DATA_IN/SEC_PIO0_2) ; also on sheet 14
P0_3: U18.H2(PIO0_3/FC0_CTS_SDA_SSEL0/CTIMER0_MAT3/FC1_SSEL2/SEC_PIO0_3) ; also on sheet 3 14
P0_4: U18.J1(PIO0_4/FC0_RTS_SCL_SSEL1/CTIMER_INP0/FC1_SSEL3/CMP0_OUT/SEC_PIO0_4) ; also on sheet 3 14
P0_5_ADC0_0: U18.F4(PIO0_5/ADC0_0/FC0_SSEL2/SCT0_GPI0/SCT0_OUT0/CTIMER_INP1/SEC_PIO0_5) ; also on sheet 14
P0_6_ADC0_8: U18.E1(PIO0_6/ADC0_8/FC0_SSEL3/SCT0_GPI1/SCT0_OUT1/CTIMER0_MAT0/SEC_PIO0_6) ; also on sheet 14
P0_7_I2S_CLK: R394.1 ; also on sheet 5 13
P0_8_I2S_WS: R395.1 ; also on sheet 5 13
P0_9_I2S_DATA: U18.L3(PIO0_9/TMS/FC1_RXD_SDA_MOSI_DATA/SCT0_GPI6/SCT0_OUT6/CTIMER1_MAT2/I2S_BRIDGE_DATA_OUT/SEC_PIO0_9) ; also on sheet 13 14
P0_10: R396.1 ; also on sheet 10
P0_11: U18.L1(PIO0_11/TDO/FC1_RTS_SCL_SSEL1/SCT0_GPI0/SCT0_OUT8/CTIMER_INP2/FC0_SSEL3/SEC_PIO0_11) ; also on sheet 1 14
P0_12: U18.E3(PIO0_12/ADC0_1/FC1_SSEL2/SCT0_GPI2/SCT0_OUT2/CTIMER_INP3/SEC_PIO0_12) ; also on sheet 3 14
P0_13: U18.G3(PIO0_13/ADC0_9/FC1_SSEL3/SCT0_GPI3/SCT0_OUT3/CTIMER0_MAT1/SEC_PIO0_13) ; also on sheet 3 14
P0_14: R397.1 ; also on sheet 10
P0_15_FC2_SCL: U18.A5(PIO0_15/FC2_TXD_SCL_MISO_WS/SCT0_GPI1/SCT0_OUT1/CTIMER2_MAT1/I2S_BRIDGE_WS_IN/SEC_PIO0_15) ; also on sheet 12 14
P0_16_FC2_SDA: U18.D6(PIO0_16/FC2_RXD_SDA_MOSI_DATA/SCT0_GPI2/SCT0_OUT2/CTIMER2_MAT2/I2S_BRIDGE_DATA_IN/SEC_PIO0_16) ; also on sheet 12 14
P0_17_FC2_SDA: U18.D7(PIO0_17/FC2_CTS_SDA_SSEL0/SCT0_GPI3/SCT0_OUT3/CTIMER2_MAT3/FC5_SSEL2/SEC_PIO0_17) ; also on sheet 10 14
P0_18_FC2_SCL: U18.B7(PIO0_18/FC2_RTS_SCL_SSEL1/SCT0_GPI6/SCT0_OUT6/CTIMER_INP4/FC5_SSEL3/SEC_PIO0_18) ; also on sheet 10 14
P0_19_ADC0_2: U18.A1(PIO0_19/ADC0_2/FC2_SSEL2/SCT0_GPI4/SCT0_OUT4/CTIMER_INP5/UTICK_CAP0/SEC_PIO0_19) ; also on sheet 14
P0_20_ADC0_10: U18.B2(PIO0_20/ADC0_10/FC2_SSEL3/SCT0_GPI5/SCT0_OUT5/CTIMER0_MAT2/CTIMER_INP11/SEC_PIO0_20) ; also on sheet 14
P0_21: U18.C7(PIO0_21/FC3_SCK/CTIMER3_MAT0/TRACECLK/SEC_PIO0_21) ; also on sheet 4
P0_22: U18.D8(PIO0_22/FC3_TXD_SCL_MISO_WS/CTIMER3_MAT1/TRACEDATA0/SEC_PIO0_22) ; also on sheet 4
P0_23_I2S_DATA_TX: U18.C9(PIO0_23/FC3_RXD_SDA_MOSI_DATA/CTIMER3_MAT2/TRACEDATA1/SEC_PIO0_23) ; also on sheet 4 13
P0_24: U18.B9(PIO0_24/FC3_CTS_SDA_SSEL0/CTIMER3_MAT3/FC2_SSEL2/TRACEDATA2/CLKOUT/SEC_PIO0_24) ; also on sheet 4
P0_25: U18.A9(PIO0_25/FC3_RTS_SCL_SSEL1/FREQME_GPIO_CLK/CTIMER_INP6/FC2_SSEL3/TRACEDATA3/CLKIN/SEC_PIO0_25) ; also on sheet 4
P0_26: U18.A2(PIO0_26/ADC0_3/FC3_SSEL2/SCT0_GPI6/SCT0_OUT6/CTIMER_INP7/SEC_PIO0_26) ; also on sheet 10
P0_27: U18.B3(PIO0_27/ADC0_11/FC3_SSEL3/SCT0_GPI7/SCT0_OUT7/CTIMER0_MAT3/SEC_PIO0_27) ; also on sheet 14
P0_28: U18.D11(PIO0_28/FC4_SCK/CTIMER4_MAT0/I2S_BRIDGE_CLK_OUT/SEC_PIO0_28) ; also on sheet 14
P0_29_FC4_TXD: U18.B10(PIO0_29/FC4_TXD_SCL_MISO_WS/CTIMER4_MAT1/I2S_BRIDGE_WS_OUT/SEC_PIO0_29) ; also on sheet 14
P0_30_FC4_RXD: U18.C11(PIO0_30/FC4_RXD_SDA_MOSI_DATA/CTIMER4_MAT2/I2S_BRIDGE_DATA_OUT/SEC_PIO0_30) ; also on sheet 14
P0_31: R398.1 ; also on sheet 10
P1_0: U18.E17(PIO1_0/FC4_RTS_SCL_SSEL1/SCT0_GPI1/SCT0_OUT7/CTIMER_INP8/FC3_SSEL3) ; also on sheet 14
P1_1: U18.G15(PIO1_1/FC4_SSEL2/SCT0_GPI2/SCT0_OUT8/CTIMER1_MAT0) ; also on sheet 10
P1_2: U18.A7(PIO1_2/CMP0_C/FC4_SSEL3/SCT0_GPI3/SCT0_OUT9/CTIMER1_MAT1) ; also on sheet 14
P1_3_SPI_CLK: U18.G16(PIO1_3/FC5_SCK) ; also on sheet 14
P1_4_SPI_MISO: U18.G17(PIO1_4/FC5_TXD_SCL_MISO_WS) ; also on sheet 3 14
P1_5_SPI_MOSI: U18.J16(PIO1_5/FC5_RXD_SDA_MOSI_DATA) ; also on sheet 3 10 14
P1_6_SPI_SS0: U18.J17(PIO1_6/FC5_CTS_SDA_SSEL0/SCT0_GPI4/SCT0_OUT4/FC4_SSEL2) ; also on sheet 3 14
P1_7: U18.J15(PIO1_7/FC5_RTS_SCL_SSEL1/SCT0_GPI5/SCT0_OUT5/CTIMER_INP9/FC4_SSEL3) ; also on sheet 3 4 14
P1_8: U18.B5(PIO1_8/ADC0_4/FC5_SSEL2/SCT0_GPI6/CTIMER_INP12/CTIMER1_MAT2) ; also on sheet 3 14
P1_9: U18.B1(PIO1_9/ADC0_12/FC5_SSEL3/SCT0_GPI7/UTICK_CAP1/CTIMER1_MAT3) ; also on sheet 14
P1_10_MCLK: U18.K16(PIO1_10/MCLK/FREQME_GPIO_CLK/CTIMER_INP10/CLKOUT) ; also on sheet 13 14
P1_11_SPI_CLK: R385.2 U18.L2(PIO1_11/HS_SPI_SCK/CTIMER2_MAT0)
P1_11_SPI_CLK_A: R385.3 ; also on sheet 11 14
P1_12_SPI_MISO: R386.2 U18.M2(PIO1_12/HS_SPI_MISO/CTIMER2_MAT1)
P1_12_SPI_MISO_A: R386.3 ; also on sheet 11 14
P1_13_SPI_MOSI: R387.2 U18.N1(PIO1_13/HS_SPI_MOSI/CTIMER2_MAT2)
P1_13_SPI_MOSI_A: R387.3 ; also on sheet 11 14
P1_14_SPI_SS0: R388.2 U18.N2(PIO1_14/HS_SPI_SSEL0/CTIMER2_MAT3)
P1_14_SPI_SS0_A: R388.3 ; also on sheet 11 14
P1_15: R86.2 SW5.6 U18.N3(PIO1_15/HS_SPI_SSEL1/CTIMER3_MAT0) ; also on sheet 14
P1_16: R87.2 SW5.5 U18.M4(PIO1_16/HS_SPI_SSEL2/SCT0_OUT8/CTIMER3_MAT1) ; also on sheet 14
P1_17: R88.2 SW5.4 U18.N4(PIO1_17/HS_SPI_SSEL3/SCT0_OUT9/CTIMER3_MAT2)
P1_18_OSPI_CLK0: R245.1 U18.T9(PIO1_18/OSPI_CLK0/SCT0_GPI0/CTIMER3_MAT3)
P1_19_OSPI_SSEL0: R240.2 R247.1 R248.1 U18.T4(PIO1_19/OSPI_SSEL0/SCT0_OUT0/CTIMER4_MAT0)
P1_20_OSPI_D0: R243.2 U18.T5(PIO1_20/OSPI_D0/SCT0_GPI1/CTIMER4_MAT1)
P1_21_OSPI_D1: R417.2 U18.U5(PIO1_21/OSPI_D1/SCT0_OUT1/CTIMER4_MAT2)
P1_22_OSPI_D2: R418.2 U18.P6(PIO1_22/OSPI_D2/SCT0_GPI2/CTIMER4_MAT3)
P1_23_OSPI_D3: R419.2 U18.P7(PIO1_23/OSPI_D3/SCT0_OUT2/CTIMER_INP8)
P1_24_OSPI_D4: R244.2 U18.T7(PIO1_24/OSPI_D4/SCT0_GPI3)
P1_25_OSPI_D5: R420.2 U18.U7(PIO1_25/OSPI_D5/SCT0_OUT3)
P1_26_OSPI_D6: R421.2 U18.R7(PIO1_26/OSPI_D6/SCT0_GPI4)
P1_27_OSPI_D7: R422.2 U18.T8(PIO1_27/OSPI_D7/SCT0_OUT4)
P1_28_OSPI_DQS: R246.1 U18.U9(PIO1_28/OSPI_DQS/SCT0_GPI5)
P1_29_OSPI_B_SCK: R352.1 U18.U3(PIO1_29/OSPI_SSEL1/SCT0_OUT5/UTICK_CAP2/CTIMER_INP13/OSPI_CLK0_N)
P1_30_SD0_CLK: U18.P10(PIO1_30/SD0_CLK/SCT0_GPI0) ; also on sheet 3
P1_31_SD0_CMD: U18.R9(PIO1_31/SD0_CMD/SCT0_GPI1) ; also on sheet 3
P2_0_SD0_D0: U18.R11(PIO2_0/SD0_D0/SCT0_GPI2) ; also on sheet 3
P2_1_SD0_D1: U18.T11(PIO2_1/SD0_D1/SCT0_GPI3) ; also on sheet 3
P2_2_SD0_D2: U18.U11(PIO2_2/SD0_D2/SCT0_OUT0) ; also on sheet 3
P2_3_SD0_D3: U18.T12(PIO2_3/SD0_D3/SCT0_OUT1) ; also on sheet 3
P2_4_SD0_WR_PRT: U18.T13(PIO2_4/SD0_WR_PRT/SCT0_OUT2/SD0_DS) ; also on sheet 3
P2_5_SD0_D4: U18.U13(PIO2_5/SD0_D4/SCT0_OUT3) ; also on sheet 3
P2_6_SD0_D5: U18.U15(PIO2_6/SD0_D5/SCT0_GPI4/CTIMER1_MAT0) ; also on sheet 3
P2_7_SD0_D6: U18.U16(PIO2_7/SD0_D6/SCT0_GPI5/CTIMER1_MAT1) ; also on sheet 3
P2_8_SD0_D7: U18.U17(PIO2_8/SD0_D7/SCT0_OUT4/CTIMER1_MAT2) ; also on sheet 3
P2_9_SD0_CD: U18.R13(PIO2_9/SD0_CARD_DET_N/SCT0_OUT5/CTIMER1_MAT3) ; also on sheet 3
P2_10_SD0_RST_N: U18.T15(PIO2_10/~{SD0_RESET}/SCT0_GPI6/CTIMER2_MAT0) ; also on sheet 3
P2_11_SD0_VOLT: U18.T16(PIO2_11/SD0_VOLT/SCT0_GPI7/CTIMER2_MAT1) ; also on sheet 3 14
P2_12: U18.T3(PIO2_12/SCT0_OUT6/CTIMER2_MAT2) ; also on sheet 4 14
P2_13: U18.T1(PIO2_13/SCT0_OUT7/CTIMER2_MAT3/CMP0_OUT) ; also on sheet 14
P2_14: U18.C1(PIO2_14/CMP0_A/SCT0_OUT8/CTIMER_INP1) ; also on sheet 14
P2_15: U18.E2(PIO2_15/CMP0_D/SCT0_OUT9/CLKIN) ; also on sheet 14
P2_16_PDM_CLK01: U18.R1(PIO2_16/PDM_CLK01) ; also on sheet 1
P2_17_PDM_CLK23: R389.2 U18.U1(PIO2_17/PDM_CLK23)
P2_17_PDM_CLK23_A: R389.3 ; also on sheet 1
P2_18_PDM_CLK45: R390.2 U18.R2(PIO2_18/PDM_CLK45)
P2_18_PDM_CLK45_A: R390.3 ; also on sheet 1
P2_19_PDM_CLK67: R384.2 U18.T2(PIO2_19/PDM_CLK67)
P2_19_PDM_CLK67_A: R384.3 ; also on sheet 1
P2_20_PDM_DATA01: U18.U2(PIO2_20/PDM_DATA01) ; also on sheet 1
P2_21_PDM_DATA23: R393.2 U18.R3(PIO2_21/PDM_DATA23/CTIMER_INP14)
P2_21_PDM_DATA23_A: R393.1 ; also on sheet 1
P2_22_PDM_DATA45: R391.2 U18.P3(PIO2_22/PDM_DATA45)
P2_22_PDM_DATA45_A: R391.3 ; also on sheet 1
P2_23_PDM_DATA67: R392.2 U18.P5(PIO2_23/PDM_DATA67)
P2_23_PDM_DATA67_A: R392.3 ; also on sheet 1
P2_24_SWO: U18.L16(PIO2_24/SWO/GPIO_INT_BMAT) ; also on sheet 12
P2_25_SWD_CLK: U18.L17(PIO2_25/SWCLK) ; also on sheet 12
P2_26_SWDIO: U18.L15(PIO2_26/SWDIO) ; also on sheet 4 12
P2_27_USB1_OVERCURRENTN: U18.M14(PIO2_27/USB1_OVERCURRENTN) ; also on sheet 2
P2_28_USB1_PWRENA: U18.N15(PIO2_28/USB1_PORTPWRN) ; also on sheet 2
P2_29_I3C0_SCL: U18.N17(PIO2_29/I3C0_SCL/SCT0_OUT0/CLKOUT) ; also on sheet 3 5 10 13
P2_30_I3C0_SDA: U18.P16(PIO2_30/I3C0_SDA/SCT0_OUT3/CLKIN/CMP0_OUT) ; also on sheet 5 10 13
P2_31_I3C0_PUR: U18.B6(PIO2_31/CMP0_B/I3C0_PUR/SCT0_OUT7/UTICK_CAP3/CTIMER_INP15/SWO) ; also on sheet 10
PIO0_7-FC1_SCK: R394.2 U18.J2(PIO0_7/TRST/FC1_SCK/SCT0_GPI4/SCT0_OUT4/CTIMER1_MAT0/I2S_BRIDGE_CLK_OUT/SEC_PIO0_7)
PIO0_8-FC1_TXD_SCL_MISO: R395.2 U18.K4(PIO0_8/TCK/FC1_TXD_SCL_MISO_WS/SCT0_GPI5/SCT0_OUT5/CTIMER1_MAT1/I2S_BRIDGE_WS_OUT/SEC_PIO0_8)
PIO0_10-FC1_CTS_SDA_SSELN0: R396.2 U18.J3(PIO0_10/TDI/FC1_CTS_SDA_SSEL0/SCT0_GPI7/SCT0_OUT7/CTIMER1_MAT3/FC0_SSEL2/SEC_PIO0_10)
PIO0_14-FC2_SCK: R397.2 U18.A3(PIO0_14/FC2_SCK/SCT0_GPI0/SCT0_OUT0/CTIMER2_MAT0/I2S_BRIDGE_CLK_IN/SEC_PIO0_14)
PIO0_31-FC4_CTS_SDA_SSELN0: R398.2 U18.A11(PIO0_31/FC4_CTS_SDA_SSEL0/SCT0_GPI0/SCT0_OUT6/CTIMER4_MAT3/FC3_SSEL2/SEC_PIO0_31)
QSPI_B_CS0: R66.2 R350.1 R364.2 R384.1
QSPI_B_DATA0: R354.1 R385.1
QSPI_B_DATA1: R355.1 R386.1
QSPI_B_DATA2: R71.1 R356.1 R387.1
QSPI_B_DATA3: R357.1 R388.1
QSPI_B_DATA4: R358.1 R389.1
QSPI_B_DATA5: R359.1 R390.1
QSPI_B_DATA6: R360.1 R391.1
QSPI_B_DATA7: R361.1 R392.1
QSPI_B_DQS: R353.1 TP44.1(TP)
RST_AP: R241.2 R242.1 U108.A4(~{RST})
RST_MX: R351.2 U19.A4(~{RESET})
RTCXIN: C69.1 U18.B17(RTCXIN) Y3.2
RTCXOUT: C62.1 U18.A17(RTCXOUT) Y3.1
SCL: R84.2 TP30.1(TP) U18.E16(PMIC_I2C_SCL) U20.5(SCL)
SCLK_AP: R245.2 U108.B2(CLK)
SCLK_MX: R352.2 U19.B2(SCLK)
SD_RST_N: R90.1 R123.2 U23.3(EN) ; also on sheet 3
SDA: R83.2 TP31.1(TP) U18.F16(PMIC_I2C_SDA) U20.6(SDA)
SIO0_AP: R243.1 U108.D3(ADQ0)
SIO0_MX: R354.2 U19.D3(SIO0/SI)
SIO1_AP: R417.1 U108.D2(ADQ1)
SIO1_MX: R355.2 U19.D2(SIO1/SO)
SIO2_AP: R418.1 U108.C4(ADQ2)
SIO2_MX: R356.2 U19.C4(SIO2)
SIO3_AP: R419.1 U108.D4(ADQ3)
SIO3_MX: R357.2 U19.D4(SIO3)
SIO4_AP: R244.1 U108.D5(ADQ4)
SIO4_MX: R358.2 U19.D5(SIO4)
SIO5_AP: R420.1 U108.E3(ADQ5)
SIO5_MX: R359.2 U19.E3(SIO5)
SIO6_AP: R421.1 U108.E2(ADQ6)
SIO6_MX: R360.2 U19.E2(SIO6)
SIO7_AP: R422.1 U108.E1(ADQ7)
SIO7_MX: R361.2 U19.E1(SIO7)
SW1_OUT: C86.1 JP29.2 L11.2 TP19.1(Pin1) U20.19(SW1_OUT)
SW2_OUT: C88.1 C316.1 JP10.1 JP12.1 JP20.1 JP25.1 JP28.2 JS12.2 L12.2 R86.1 R87.1 R88.1 TP20.1(Pin1) U20.3(SW2_OUT) ; also on sheet 1 3 4 5 10 11 13 14
SW2_OUT_MCU: C111.1 C116.1 C120.1 C121.1 C122.1 JP20.2 U18.F5(VDDIO_0_1) U18.H5(VDDIO_0_2) U18.K5(VDDIO_0_3) U18.M5(VDDIO_0_4) U18.N6(VDDIO_0_5) U18.N8(VDDIO_0_6) U18.N10(VDDIO_0_7)
SYSRST_B: R82.2 U20.11(~{SYSRST}) ; also on sheet 4
TAB: U14.4(TAB)
TEMP_SEN: RT1.1 TP28.1(TP) U20.14(TS)
USB0_DM_TRGT: U18.T17(USB1_DM) ; also on sheet 2 3
USB0_DP_TRGT: U18.R17(USB1_DP) ; also on sheet 2 3
USB1_VDD3V3: SH4.2 U18.N16(USB1_VDD3V3)
USDHC_SPWR: JS14.1 R121.1 ; also on sheet 3
VREF_H: C68.1 JP10.2 U18.D2(VREFP)
VREF_L: C68.2 JP9.1 U18.C2(VREFN)
VSYS: C79.1 C81.1 C87.1 TP18.1(TP) U20.2(PSYS2) U20.17(ASYS) U20.20(PSYS1)
XTALIN: C59.1 R56.1 U18.B14(XTALIN) Y2.1
XTALOUT: C58.1 R56.2 U18.B13(XTALOUT) Y2.3
N17774863: R93.1 SW5.1
N17774865: R94.1 SW5.2
N17774867: R95.1 SW5.3
N19526530: JP22.1 R149.2
N19526548: JP22.3 R61.1
N19527680: D15.A(ANODE) R121.2
N19531396: D11.A(ANODE) R98.2
N19546738: R251.1 TP43.1(TP)
N19546803: R249.2 U108.A2(NC_1)
N19546823: R250.2 U108.A5(NC_2)
N19546843: R251.2 U108.B1(NC_3)
N19546881: R247.2 U108.C2(RSU)
N19830189: R363.2 U19.A2(NC)
N19830205: R365.1 U19.B1(DNU)
N19830207: R365.2 TP45.1(TP)
N19830220: R364.1 U19.A3(NC)
N19830414: R362.2 U19.A5(~{ECS})
N20219970: R393.3 TP46.1(TP)

Not connected (* = marked no-connect by the designer): U19 B5(DNU)* C5(NC)*; U108 B5(NC_4)* C5(NC_5)*

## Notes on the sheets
sheet 7
- PMIC
- PCA9420's ON# Pin have Internal Pull-up
  Resistor is Not Required
- i
- Programmable Output Voltage Regulation:
  ===============================
  1. SW1: Core Buck, 0.5V~1.5V Output, 25mV/step, up to 250mA
  2. SW2: System Buck, 1.5V~2.1V/2.7V~3.3V Output, 25mV/step, up to 500mA
  3. LDO1: Always-ON LDO, 1.70V~1.90V Output, 25mV/step, up to 1mA
  4. LDO2: System LDO, 1.5V~2.1V/2.7V~3.3V Output, 25mV/step, up to 250mA
- 3.3V LDO Supply
- LDO2_OUT = VDD_TARGET = 3.3V
- VDDA_ADC3V3 & USB1_VDD3V3  = 3.3V
- 2.5V Supply
- Max output current from
  NCP692 is 1A
- 24MHZ
- RED LED
- Link 2.5v Power
- POWER-ON INDICATOR
- 2.5V- NCP1117ST25T3G
  3.3V- NCP1117ST33T3G
- 3.3V SD Card Supply
- 32.768KHZ
- Max output current from
  NCP692 is 1A
- RED LED
- DEBUG
  GND HOOK
- GND TP
sheet 8
- LDO2_OUT (3.3v)
- SW2_OUT (1.8V)
- BOOT CONFIG
- CAD NOTE: ADD SILKSCREEN ISP1, ISP2 & ISP3
sheet 9
- OCTAL FLASH
- M
- Frequency max = 166MHz
  Data DDR feature
- F
- G
- H
- K
- OCTO-SPI0 RST
- A
- B
- OD
- OCTO-SPI0_B_CLK
- C
- D
- J
- E1
- OD
- E1
- L
- for S27
- E1
- E1
- E2
- E2
- E2
- E2
- OSPI/pSRAM
- Populated
- DNP
- This footprint supports:
  1. S26KS256SDPBHV02
  2. S27KS0641DPBHI023 (pin2pin with 3)
  3. APS6408L-OBM-BA (pin2pin with 2)
  4. MX25UM51345GXDI00
- Schematic Note: MX25UM51345GXDI00
  Typical values at VCC= 1.8V  (VCC = 1.65V ~ 2.0V)
  Output High Voltage = VCC-0.2
  Input High Voltage = VCC+0.4
- MX25UM51345GXDI00
- A,B,C,D,E1,E2,F,G,H,M
- J,K,L
- S26KS256SDPBHV02
- S27KS0641DPBHI023
- A,B,C,D,E1,E2,F,G,H,J,K,M
- B,C,D,E1,E2,F,G,J,L,M
- H,K
- L
- APS6408L-OBM-BA
- B,C,D,E1,E2,F,G,J,L,M
- H,K
- OCTO-SPI0_B_SSEL0
- pSRAM
- OCTO-SPI0_B_D0
- OCTO-SPI0_B_D1
- OCTO-SPI0_B_D2
- for testing
- OCTO-SPI0_B_D3
- for testing
- Frequency max = 200MHz or 133MHz
- for testing
- Data DDR feature
- for S26
- OCTO-SPI0_B_D4
- for S26
- for S26/7
- OCTO-SPI0_B_D5
- for S26
- for testing
- OCTO-SPI0_B_D6
- This footprint supports:
  1. S26KS256SDPBHV02
  2. S27KS0641DPBHI023 (pin2pin with 3)
  3. APS6408L-OBM-BA (pin2pin with 2)
  4. MX25UM51345GXDI00
- APS6408L-OBx_BGA24L
  APS6408L-OBM-BA
- OCTO-SPI0_B_D7
- Close to Octal FLASH
